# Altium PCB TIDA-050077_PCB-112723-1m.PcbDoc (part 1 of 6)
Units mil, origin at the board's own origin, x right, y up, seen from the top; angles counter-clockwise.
Board outline 3780 x 7750 mil, 16 copper layers (Top Layer, L2-Powet 1, L3-Power 2, L4-Power 3, L5-Power 4, L6-INT 1, L7-INT 2, L8-INT 3, L9-INT 4, L10-INT 5, L11-INT 6, L12-Power 5, L13-Power 6, L14-Power 7, L15-Power 8, Bottom Layer), stack 121.442 mil thick; 381 components, 136 nets, 958 pads, 3470 vias.
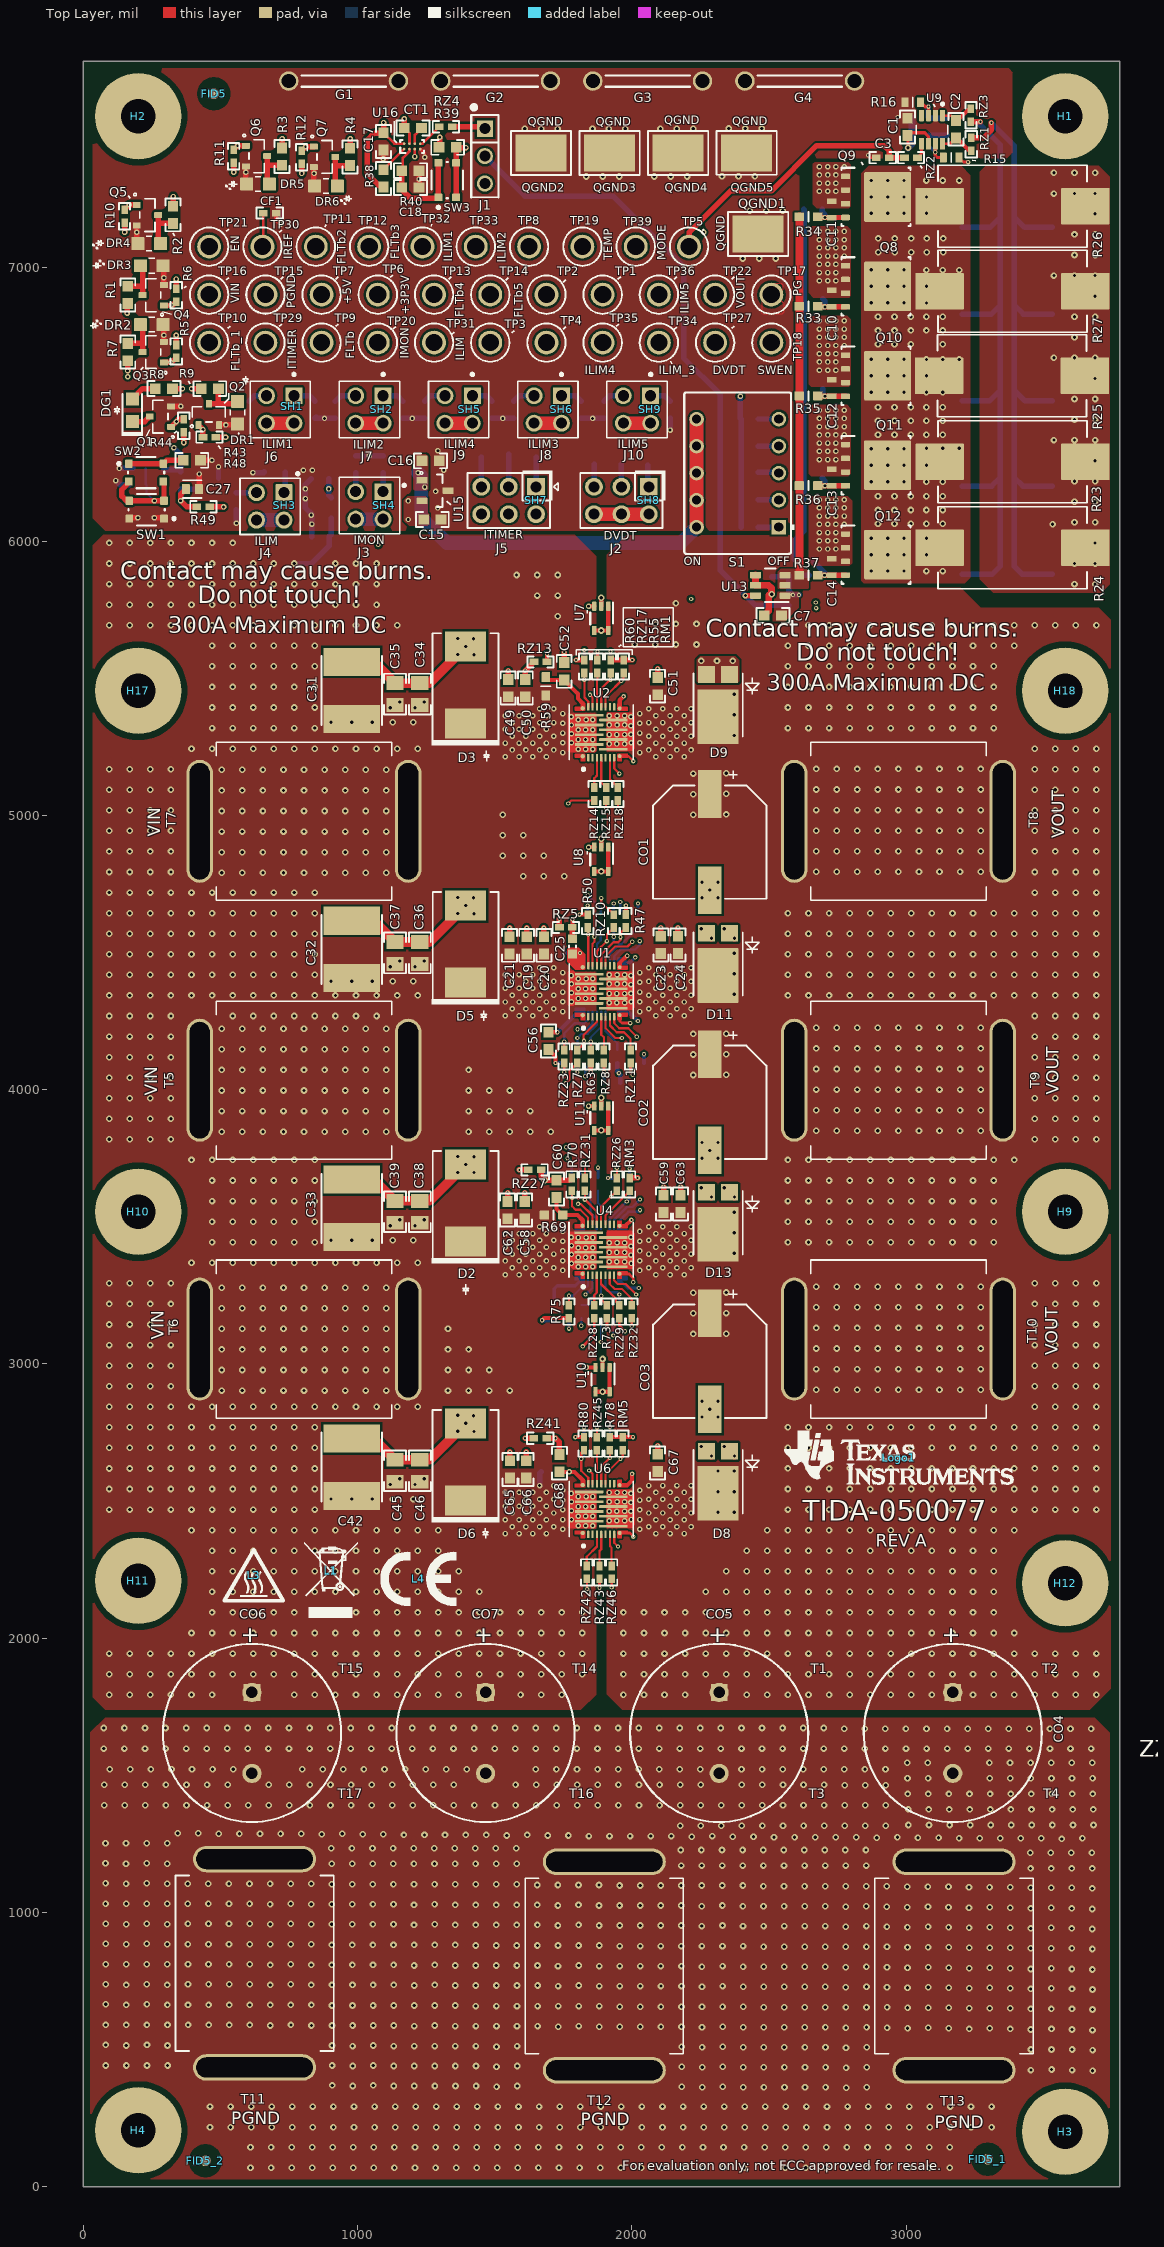
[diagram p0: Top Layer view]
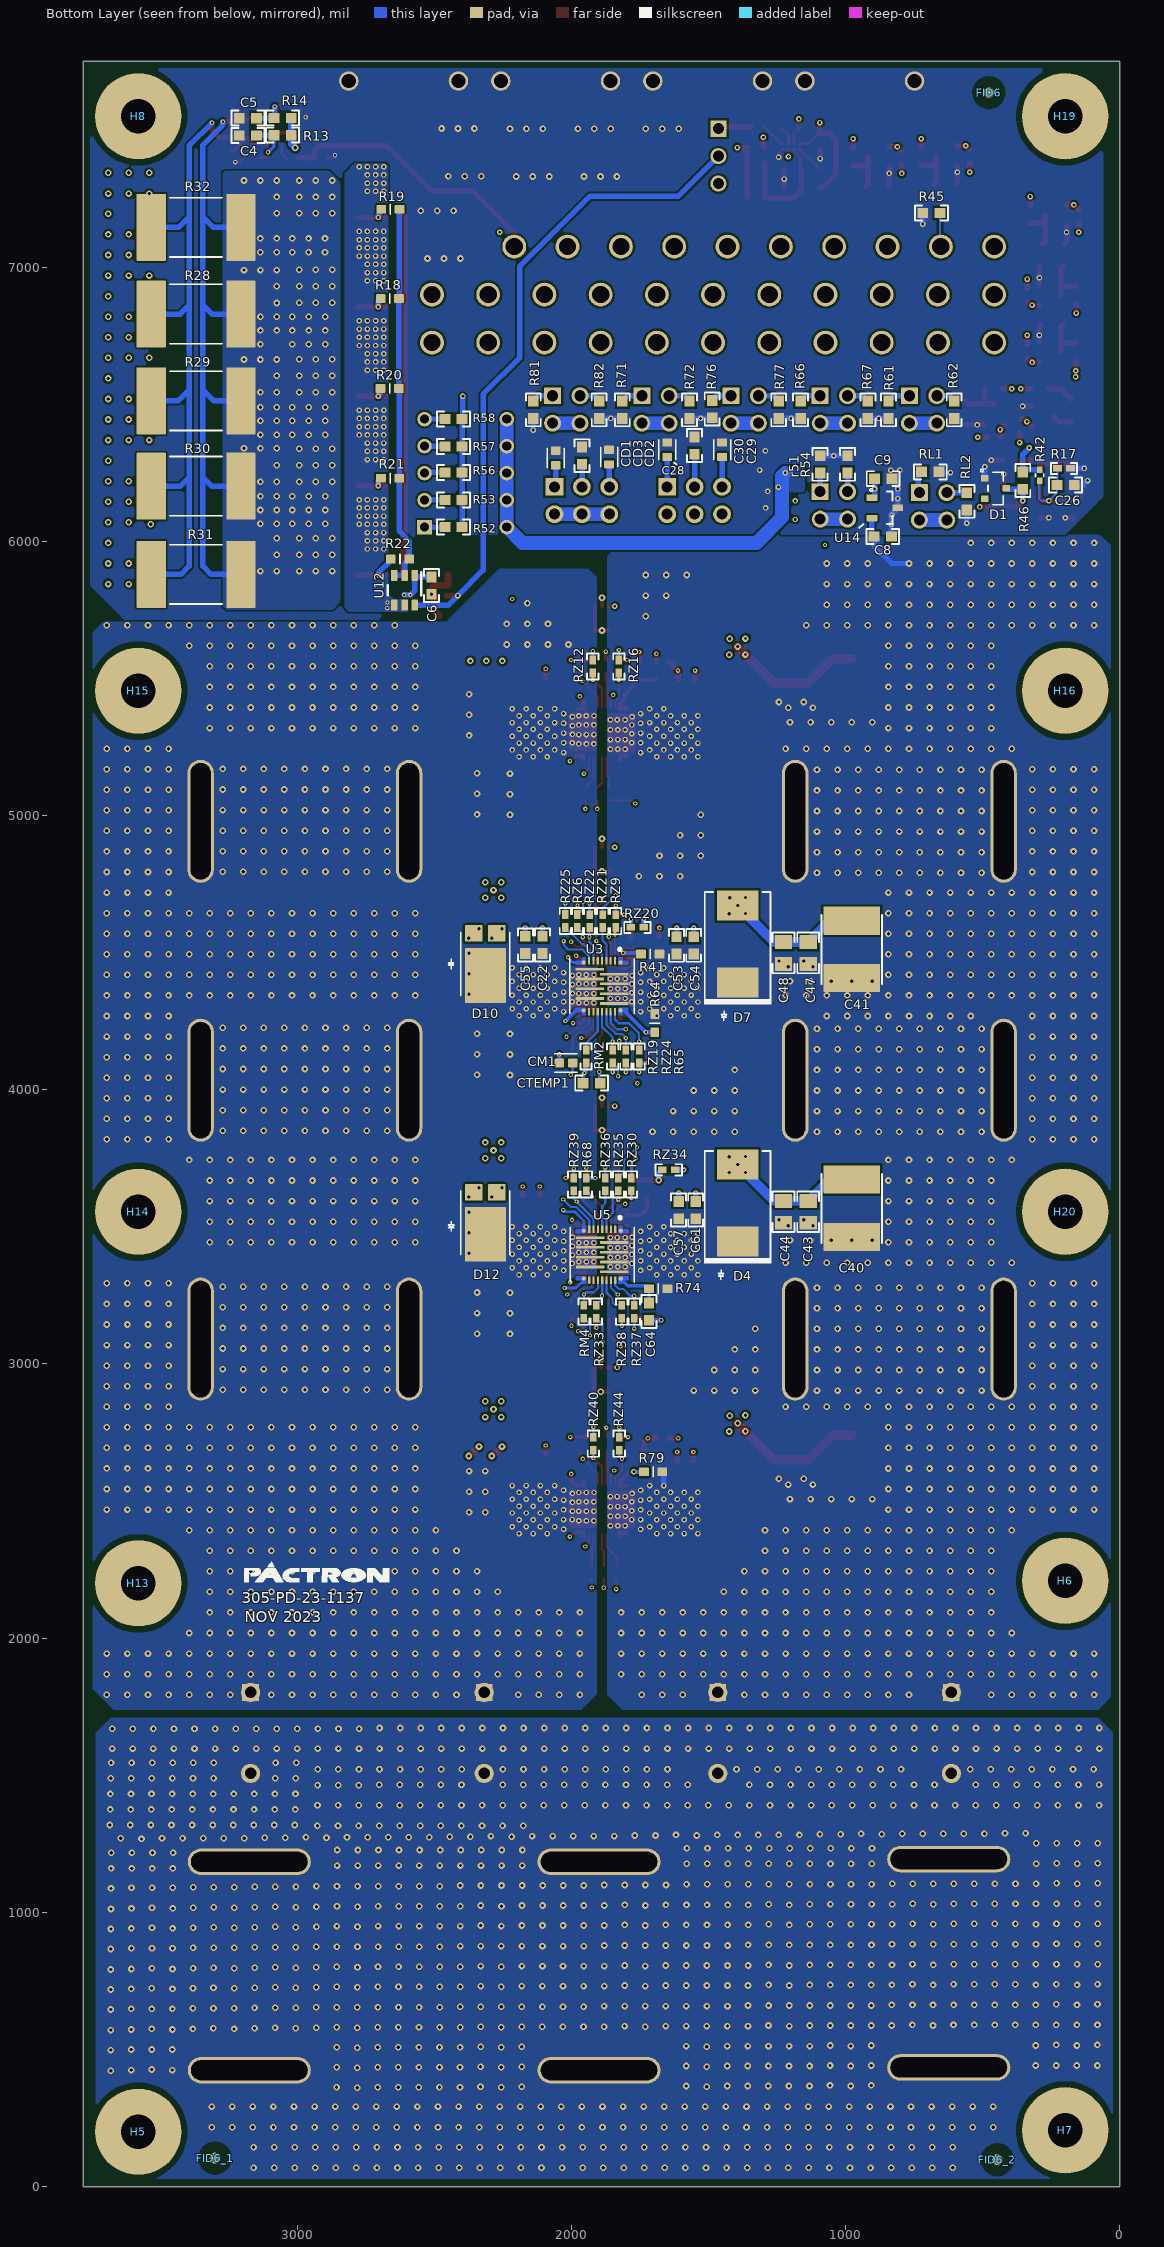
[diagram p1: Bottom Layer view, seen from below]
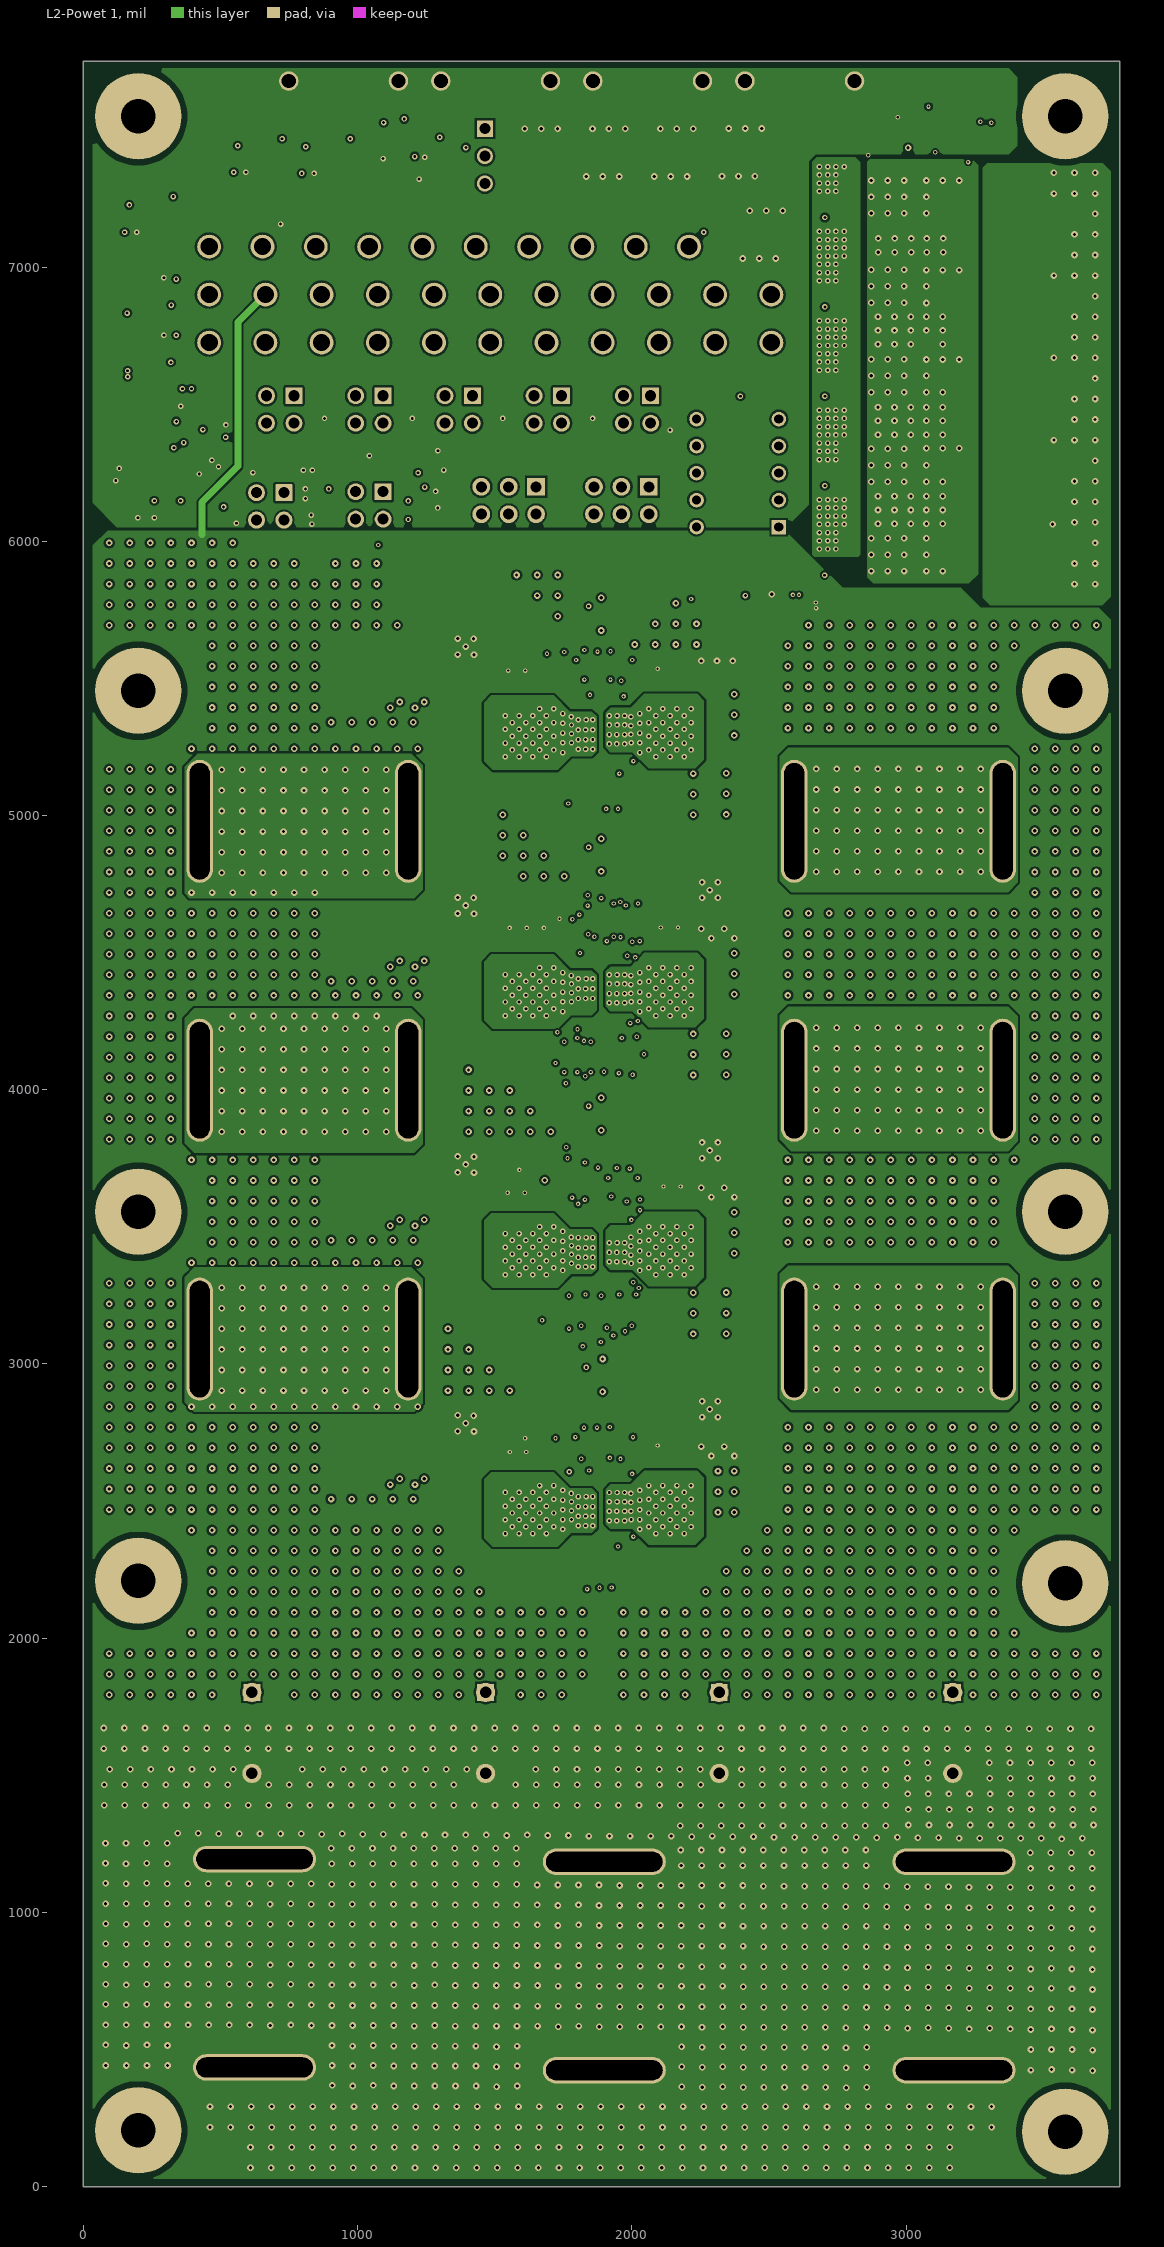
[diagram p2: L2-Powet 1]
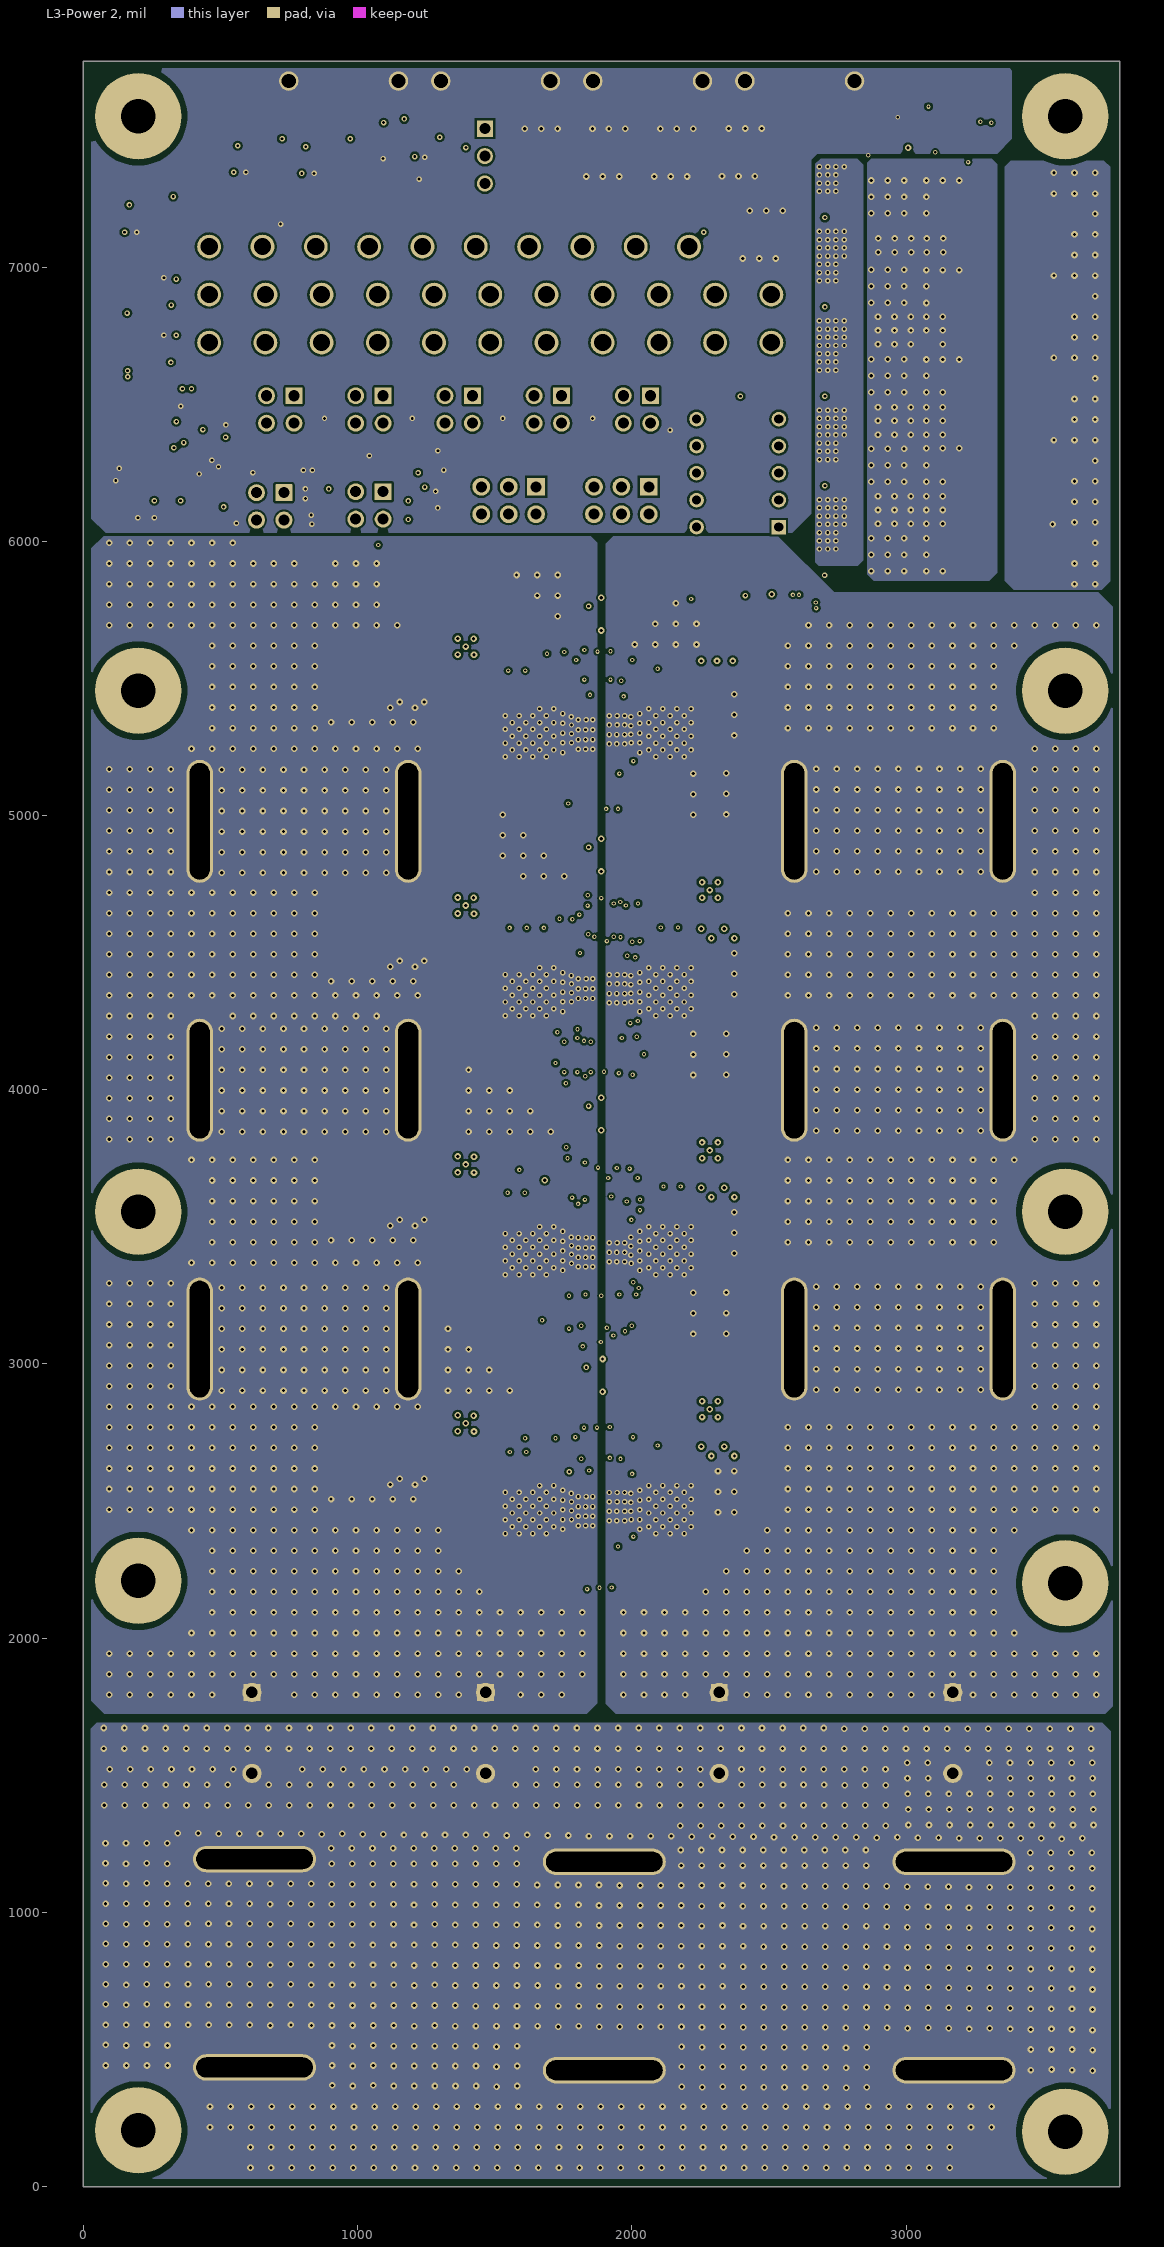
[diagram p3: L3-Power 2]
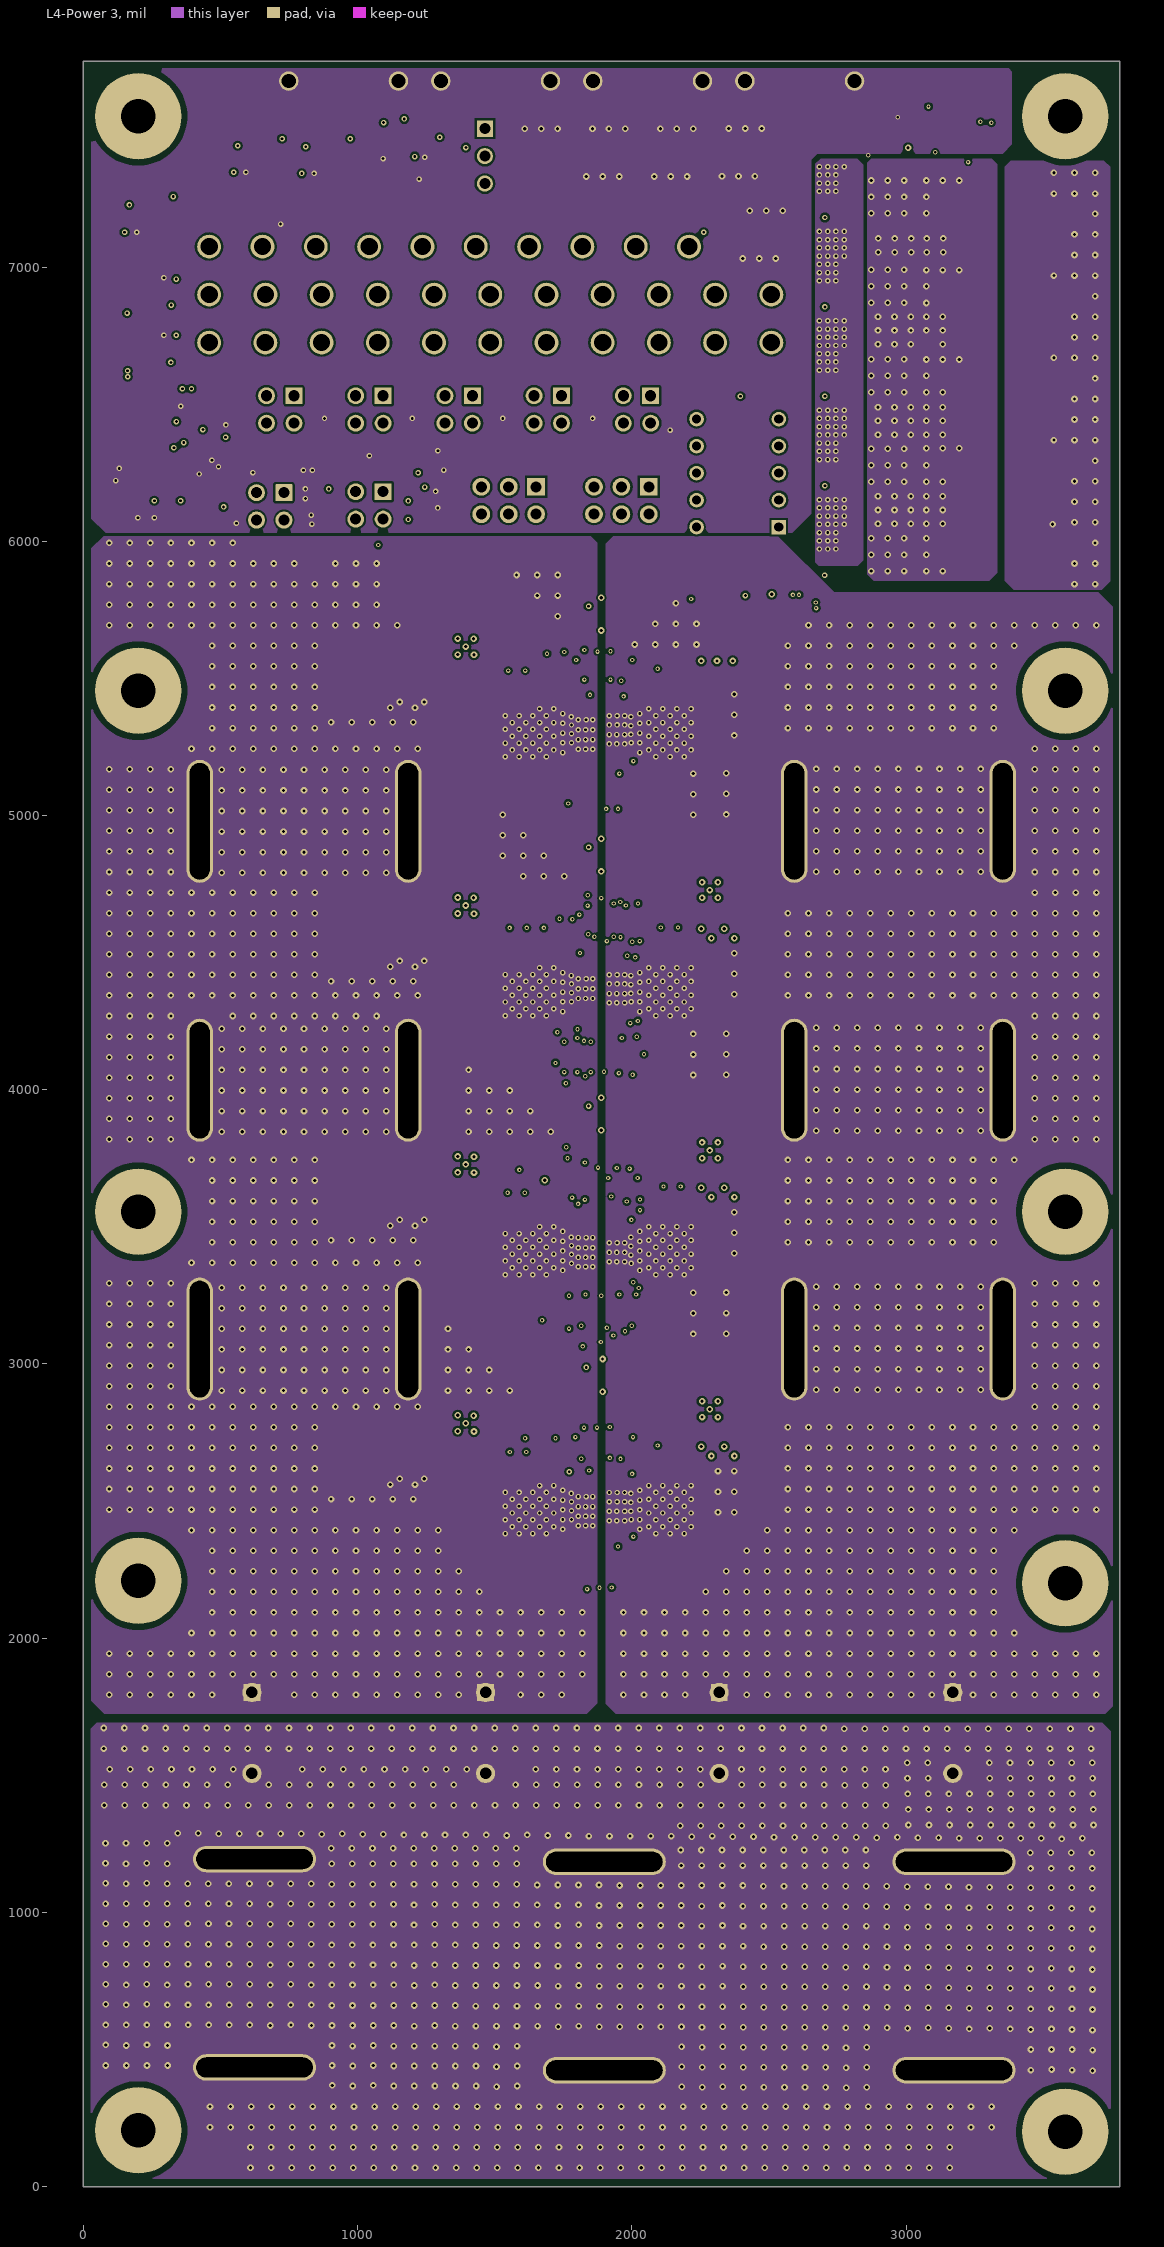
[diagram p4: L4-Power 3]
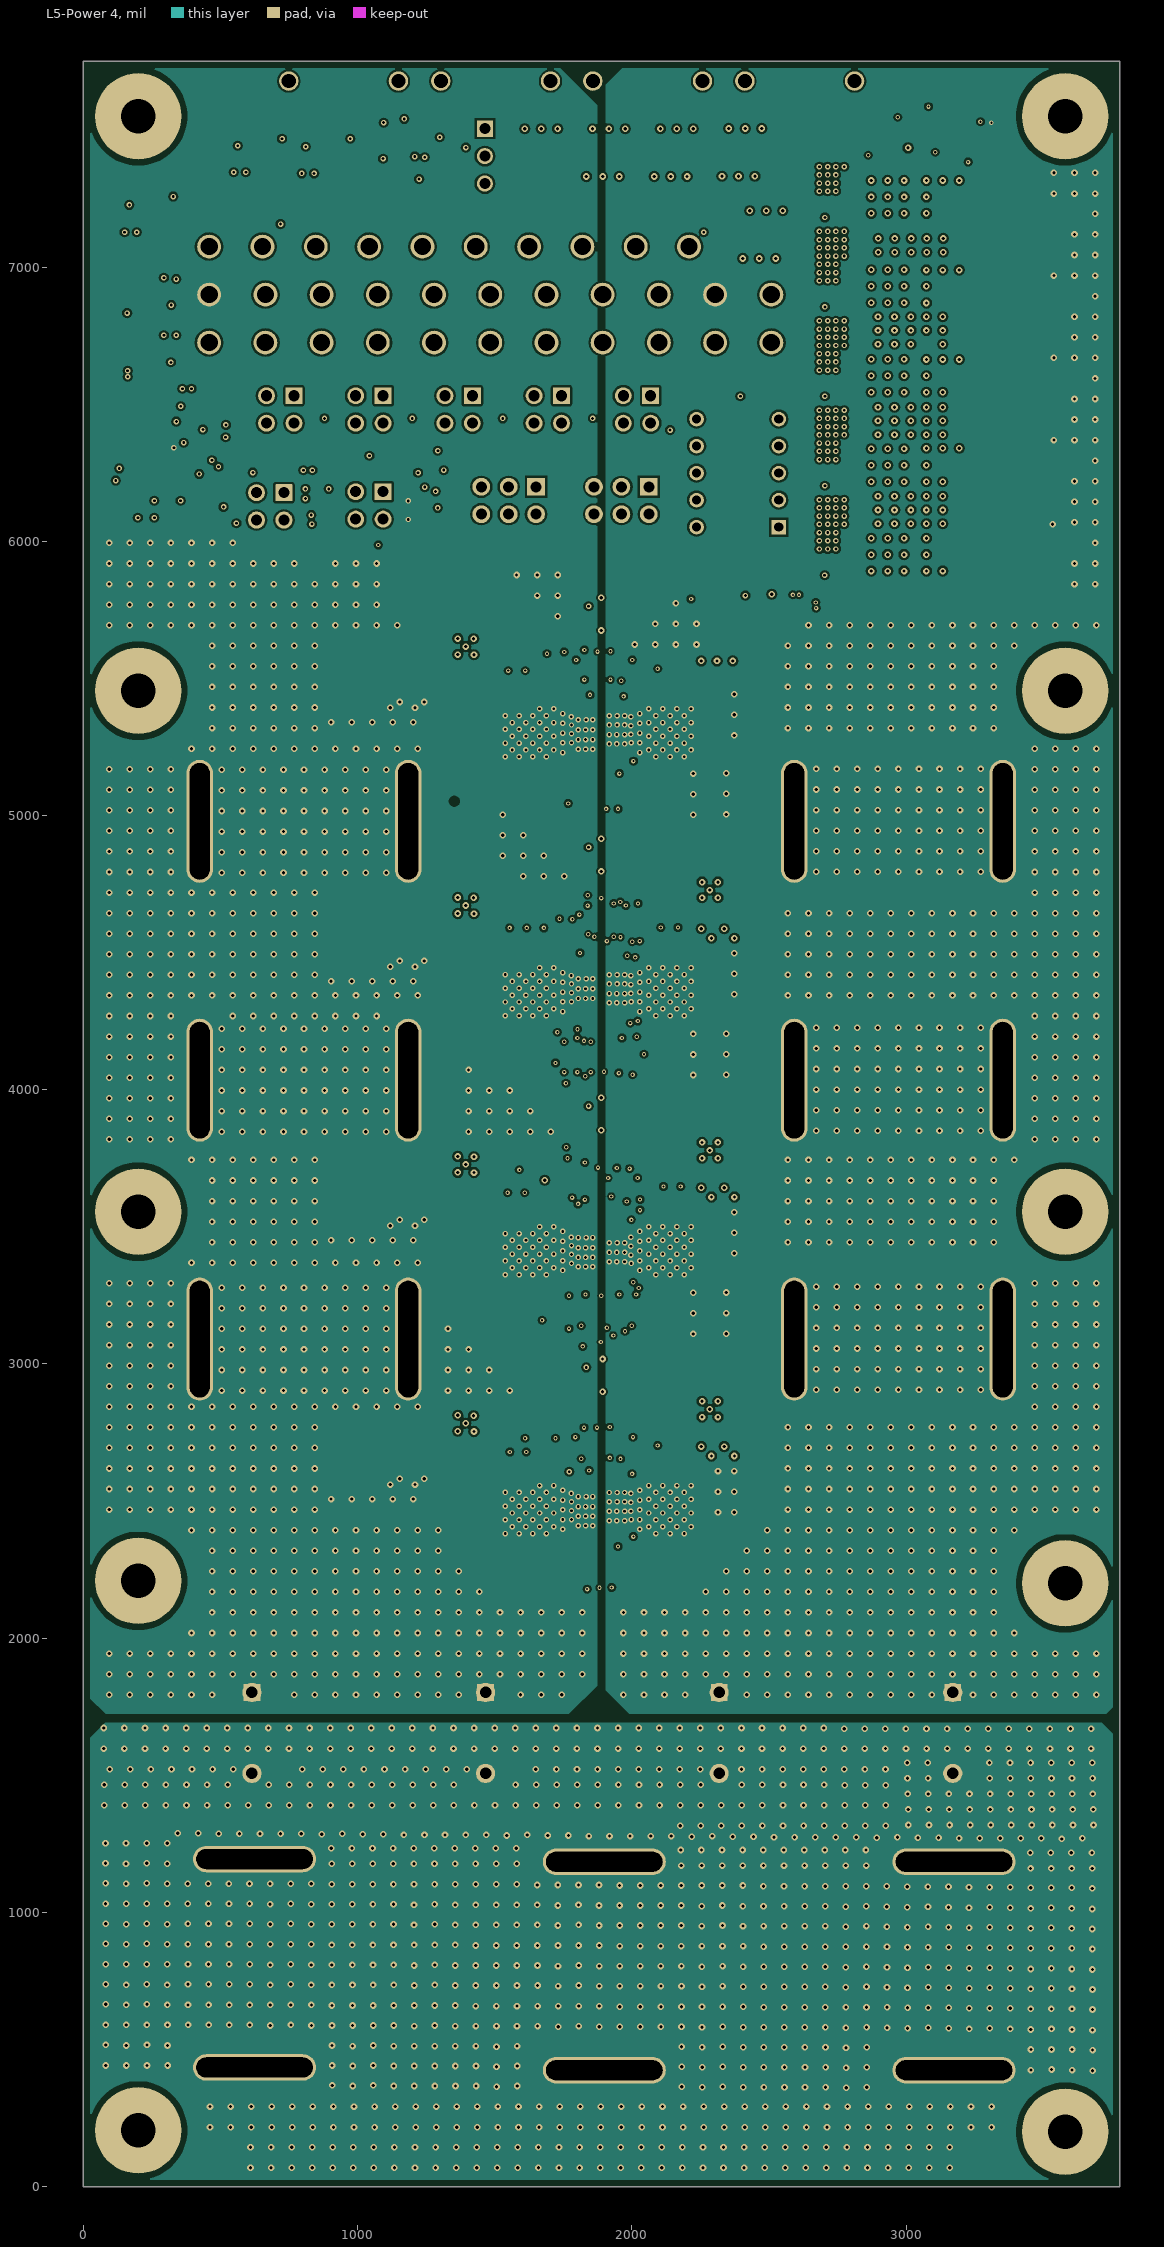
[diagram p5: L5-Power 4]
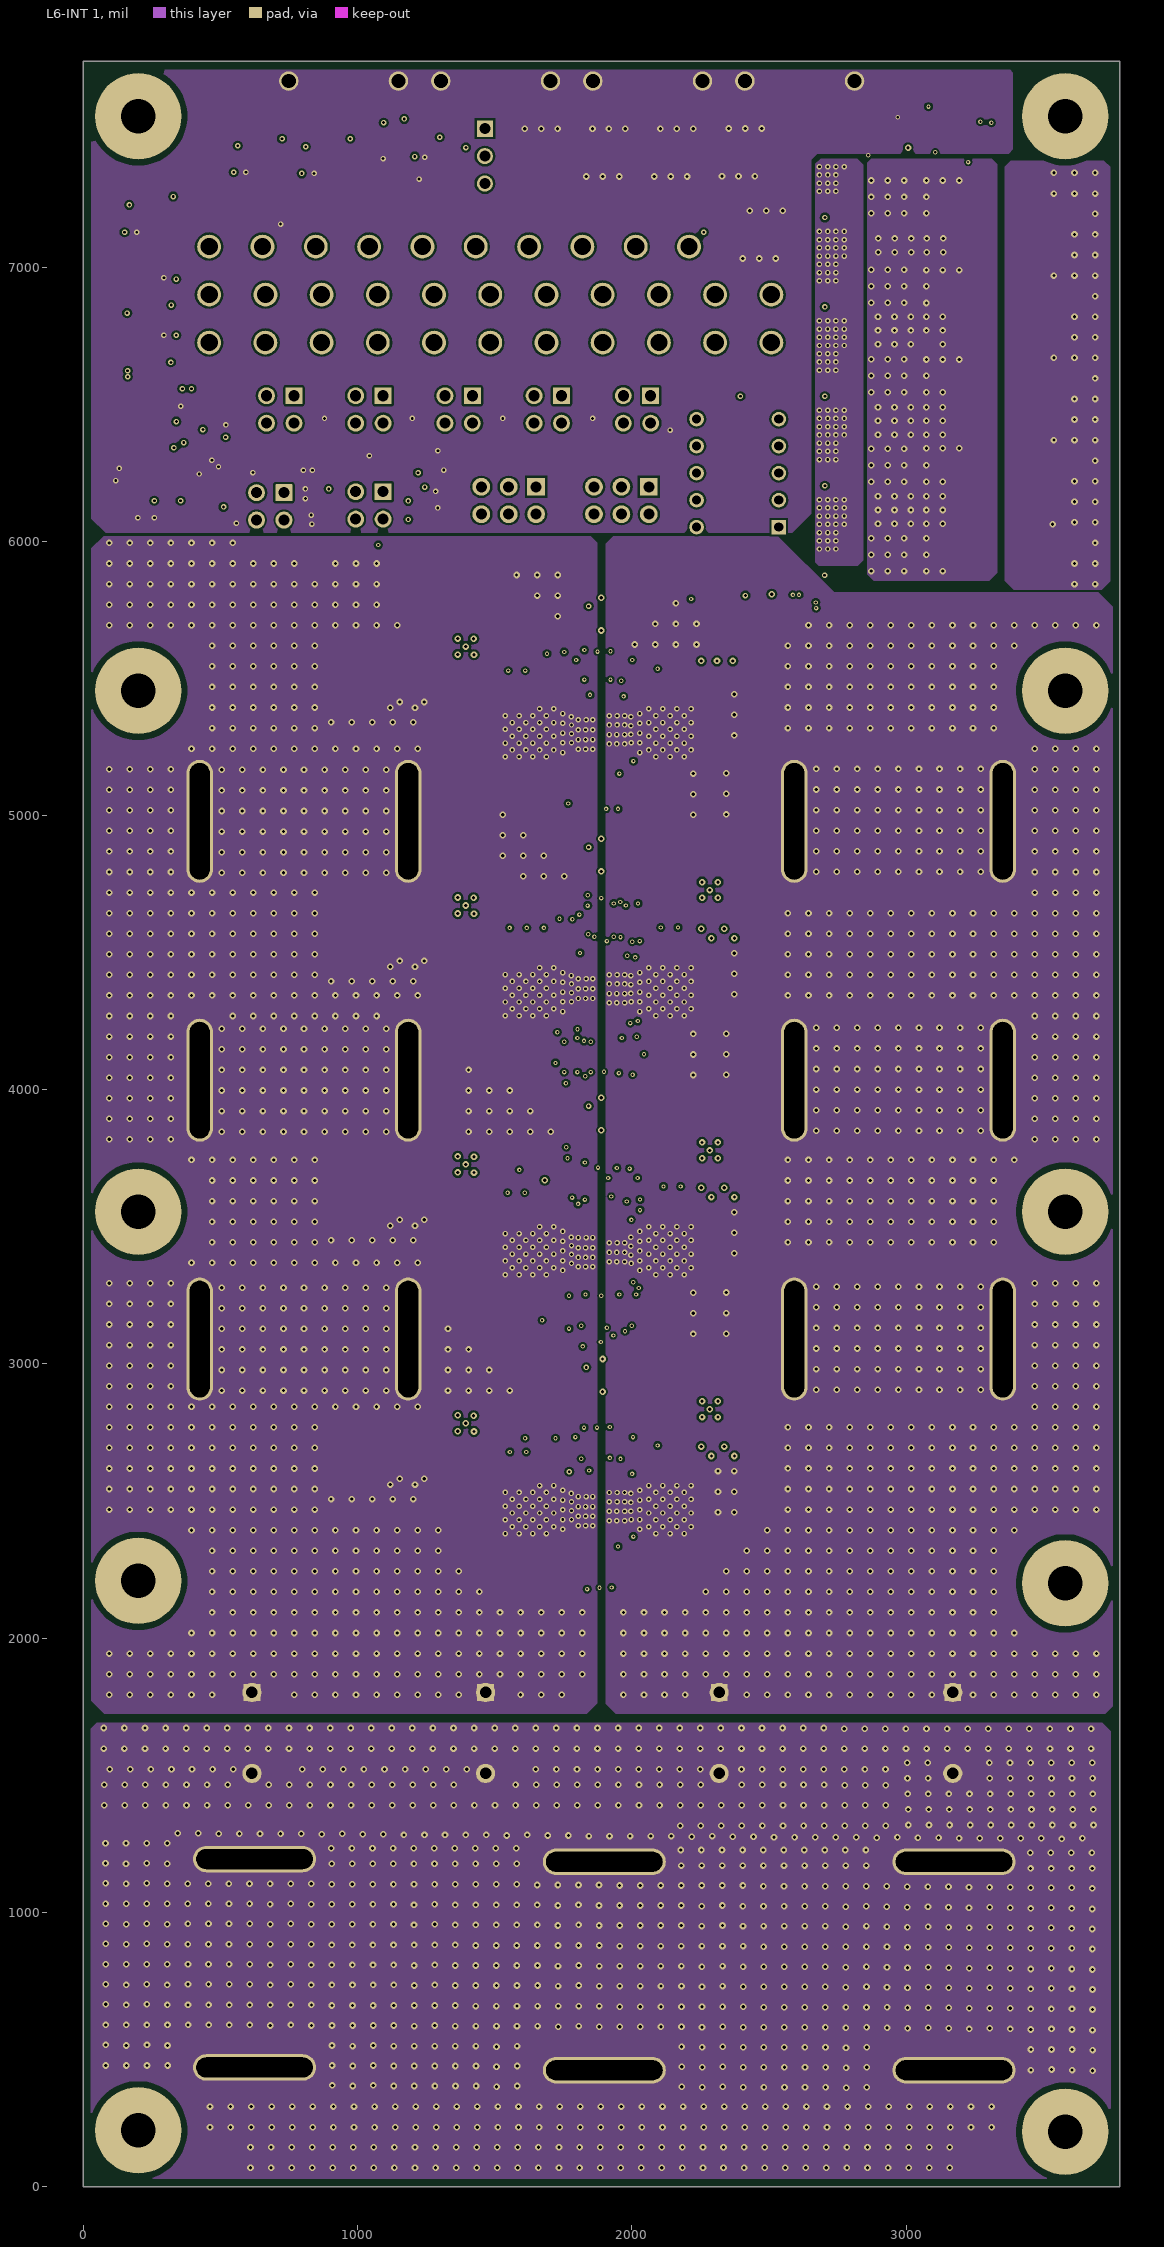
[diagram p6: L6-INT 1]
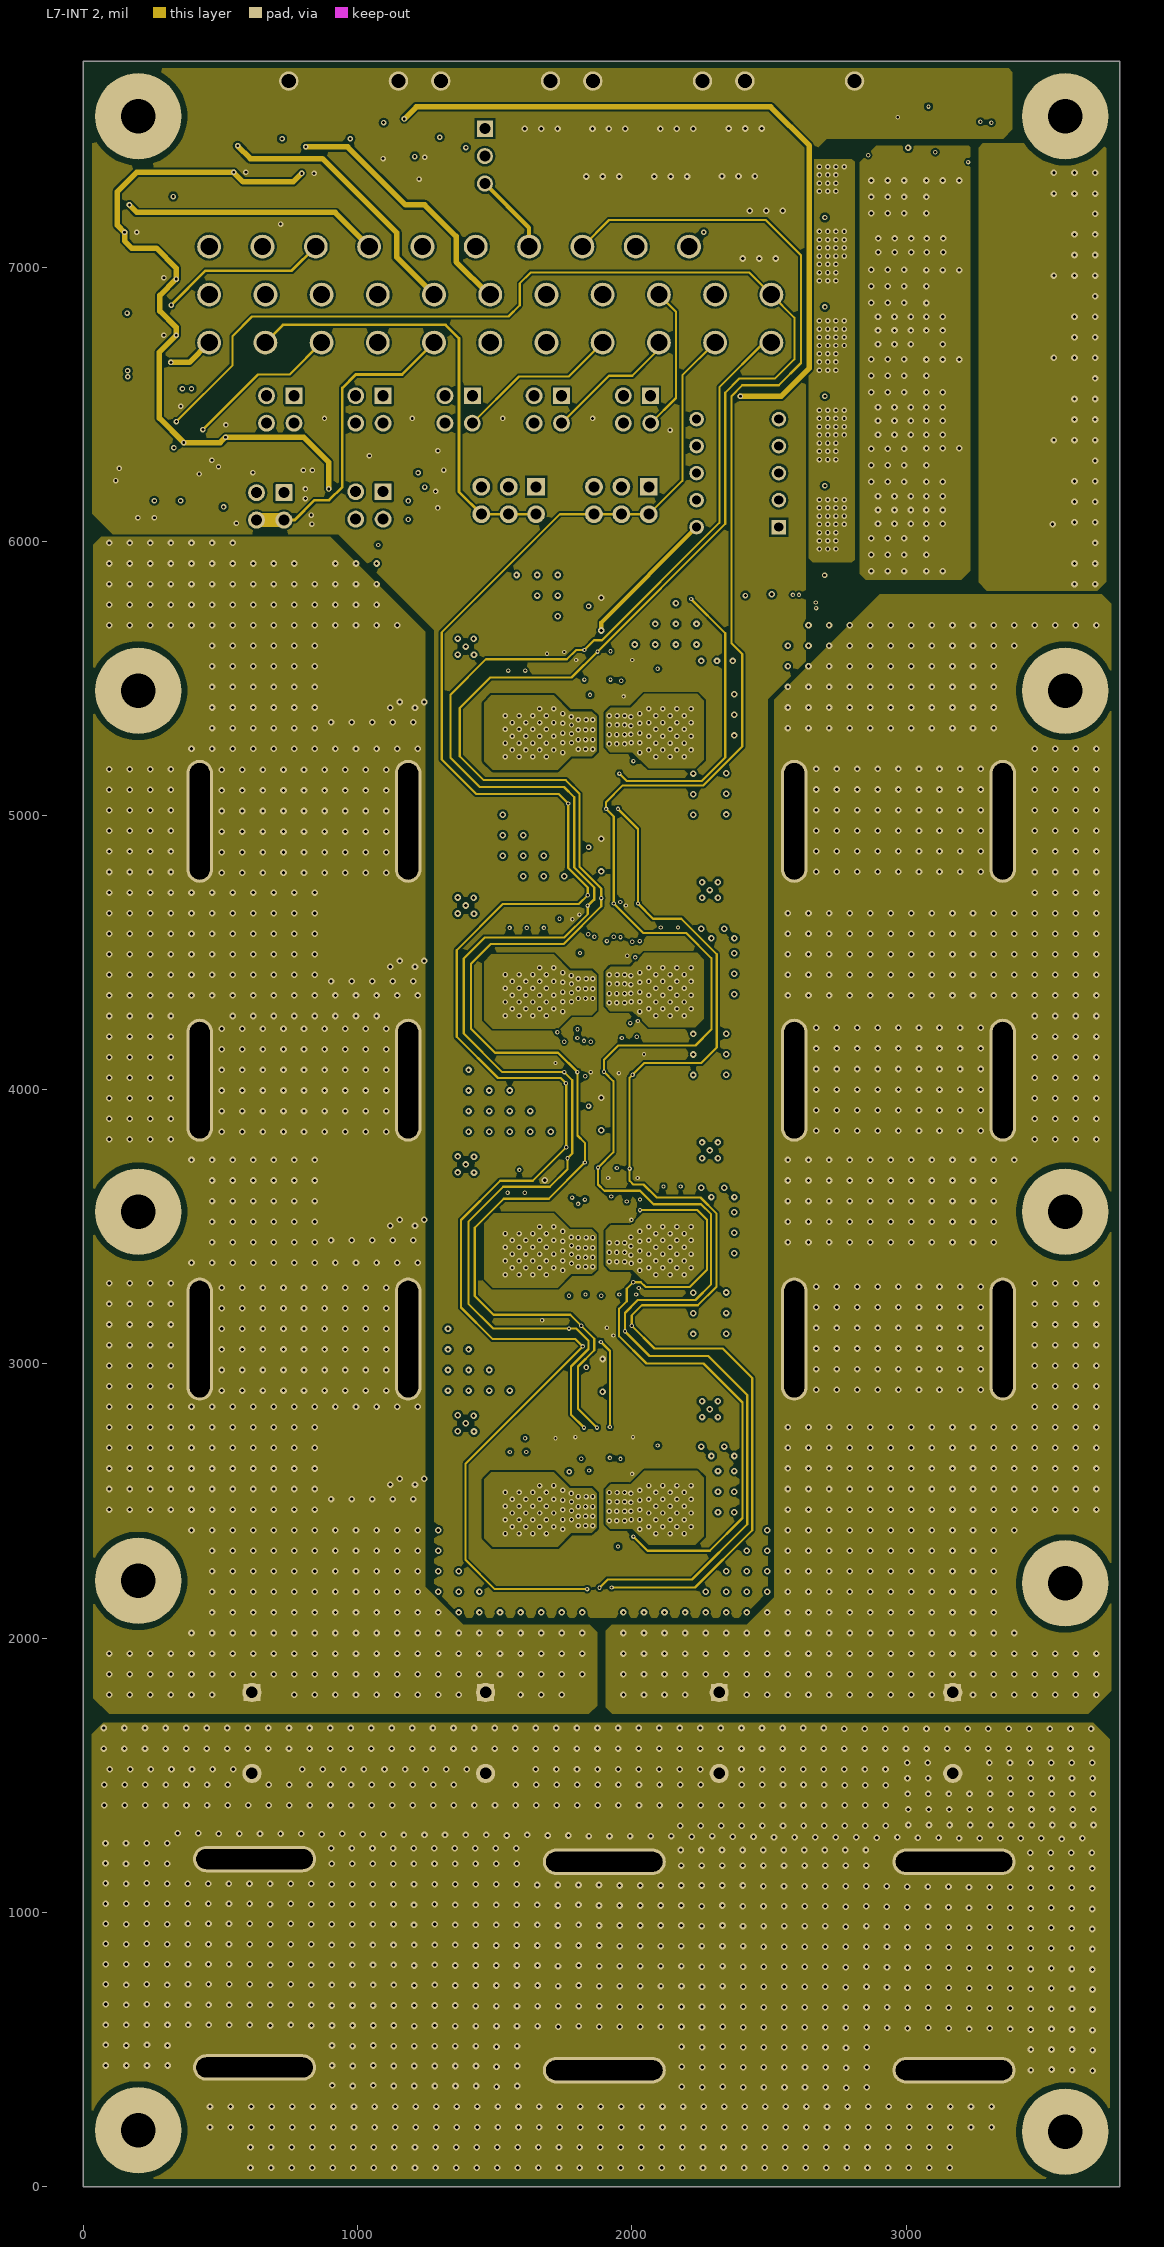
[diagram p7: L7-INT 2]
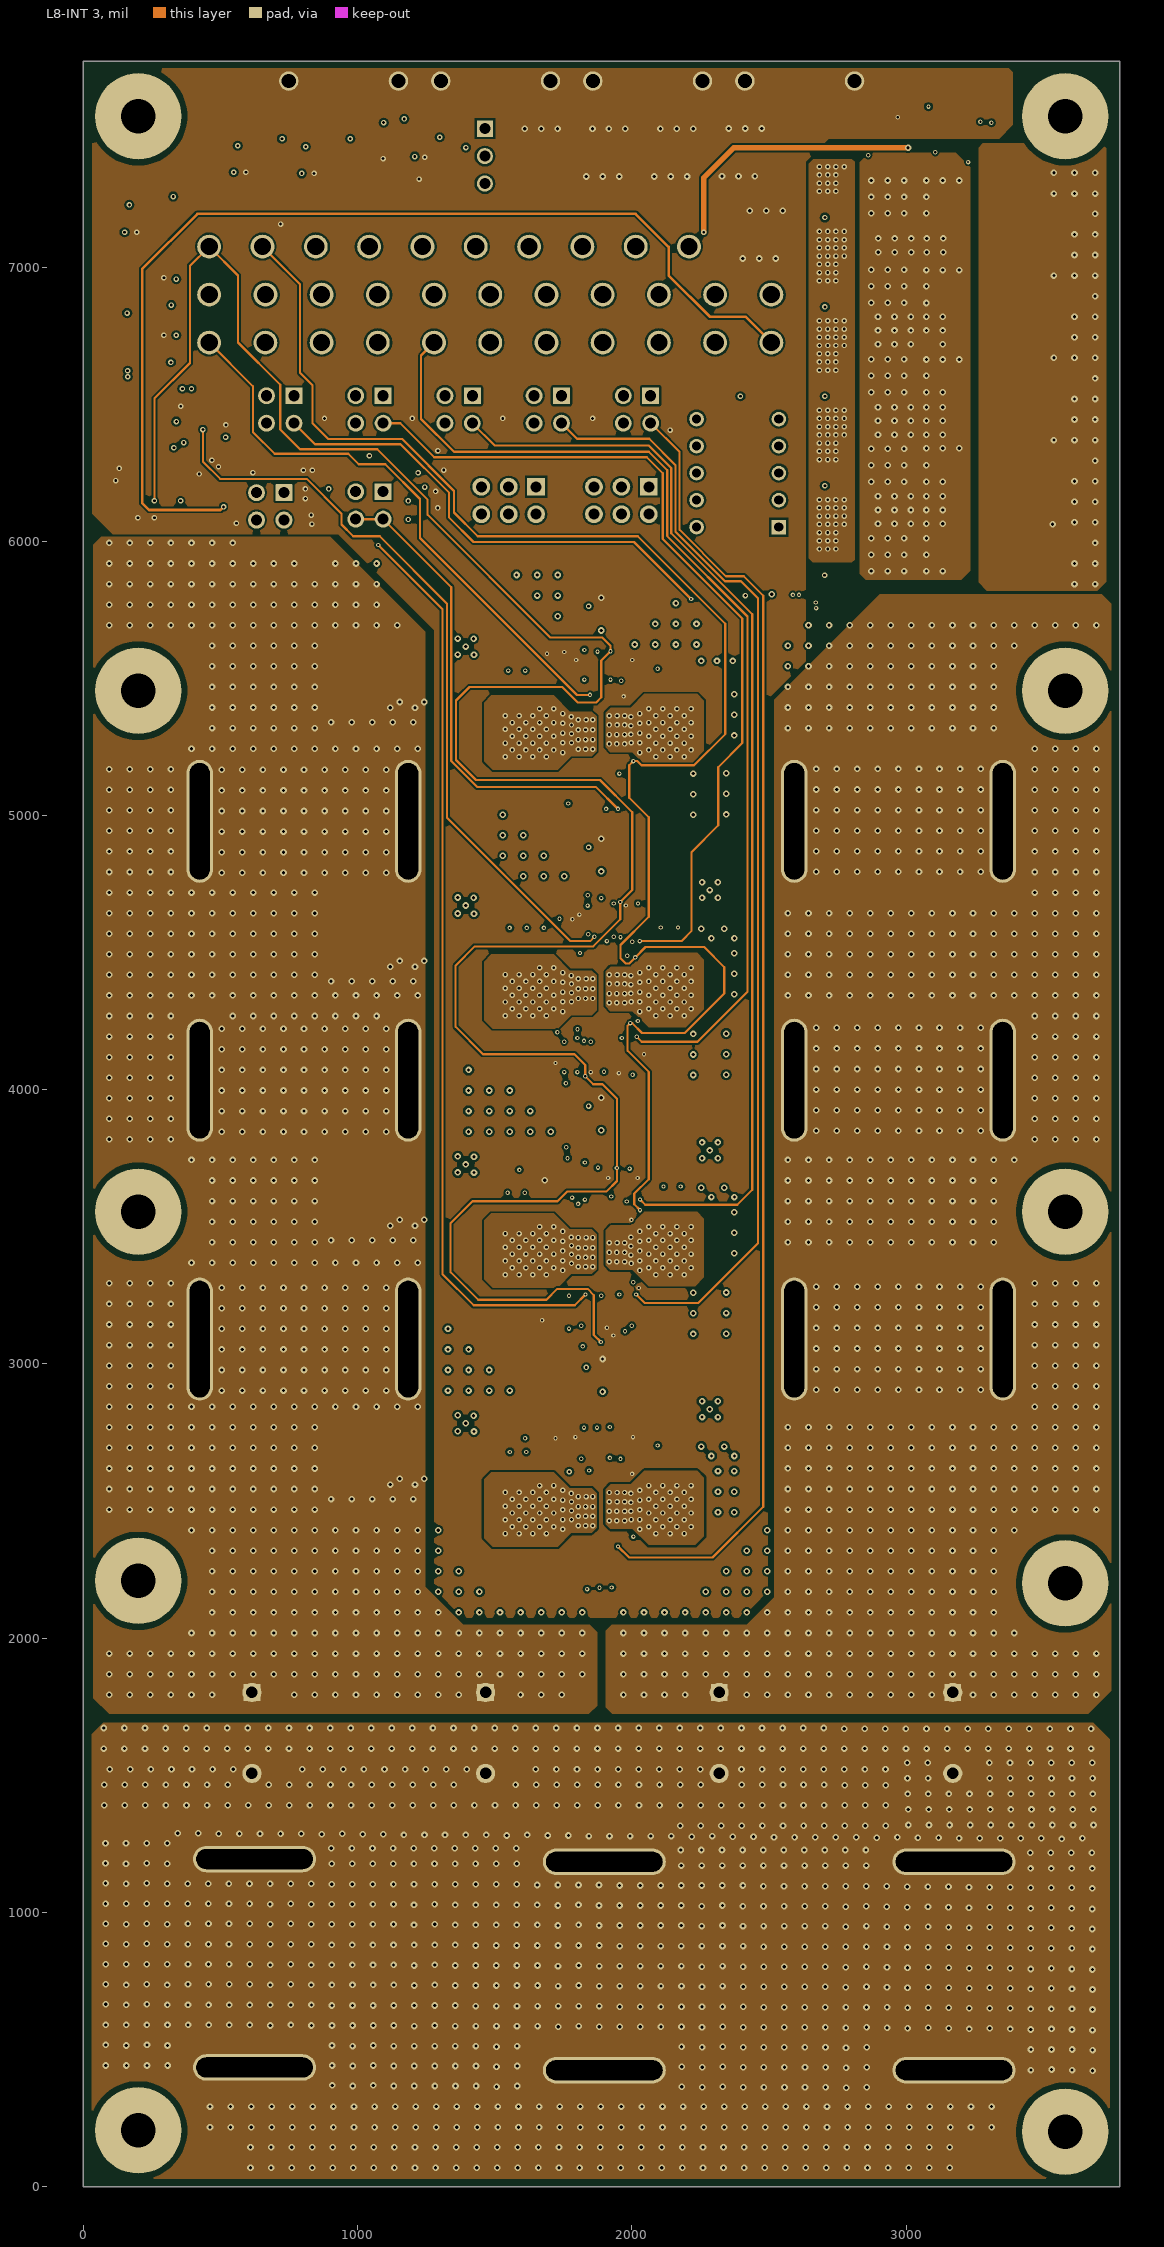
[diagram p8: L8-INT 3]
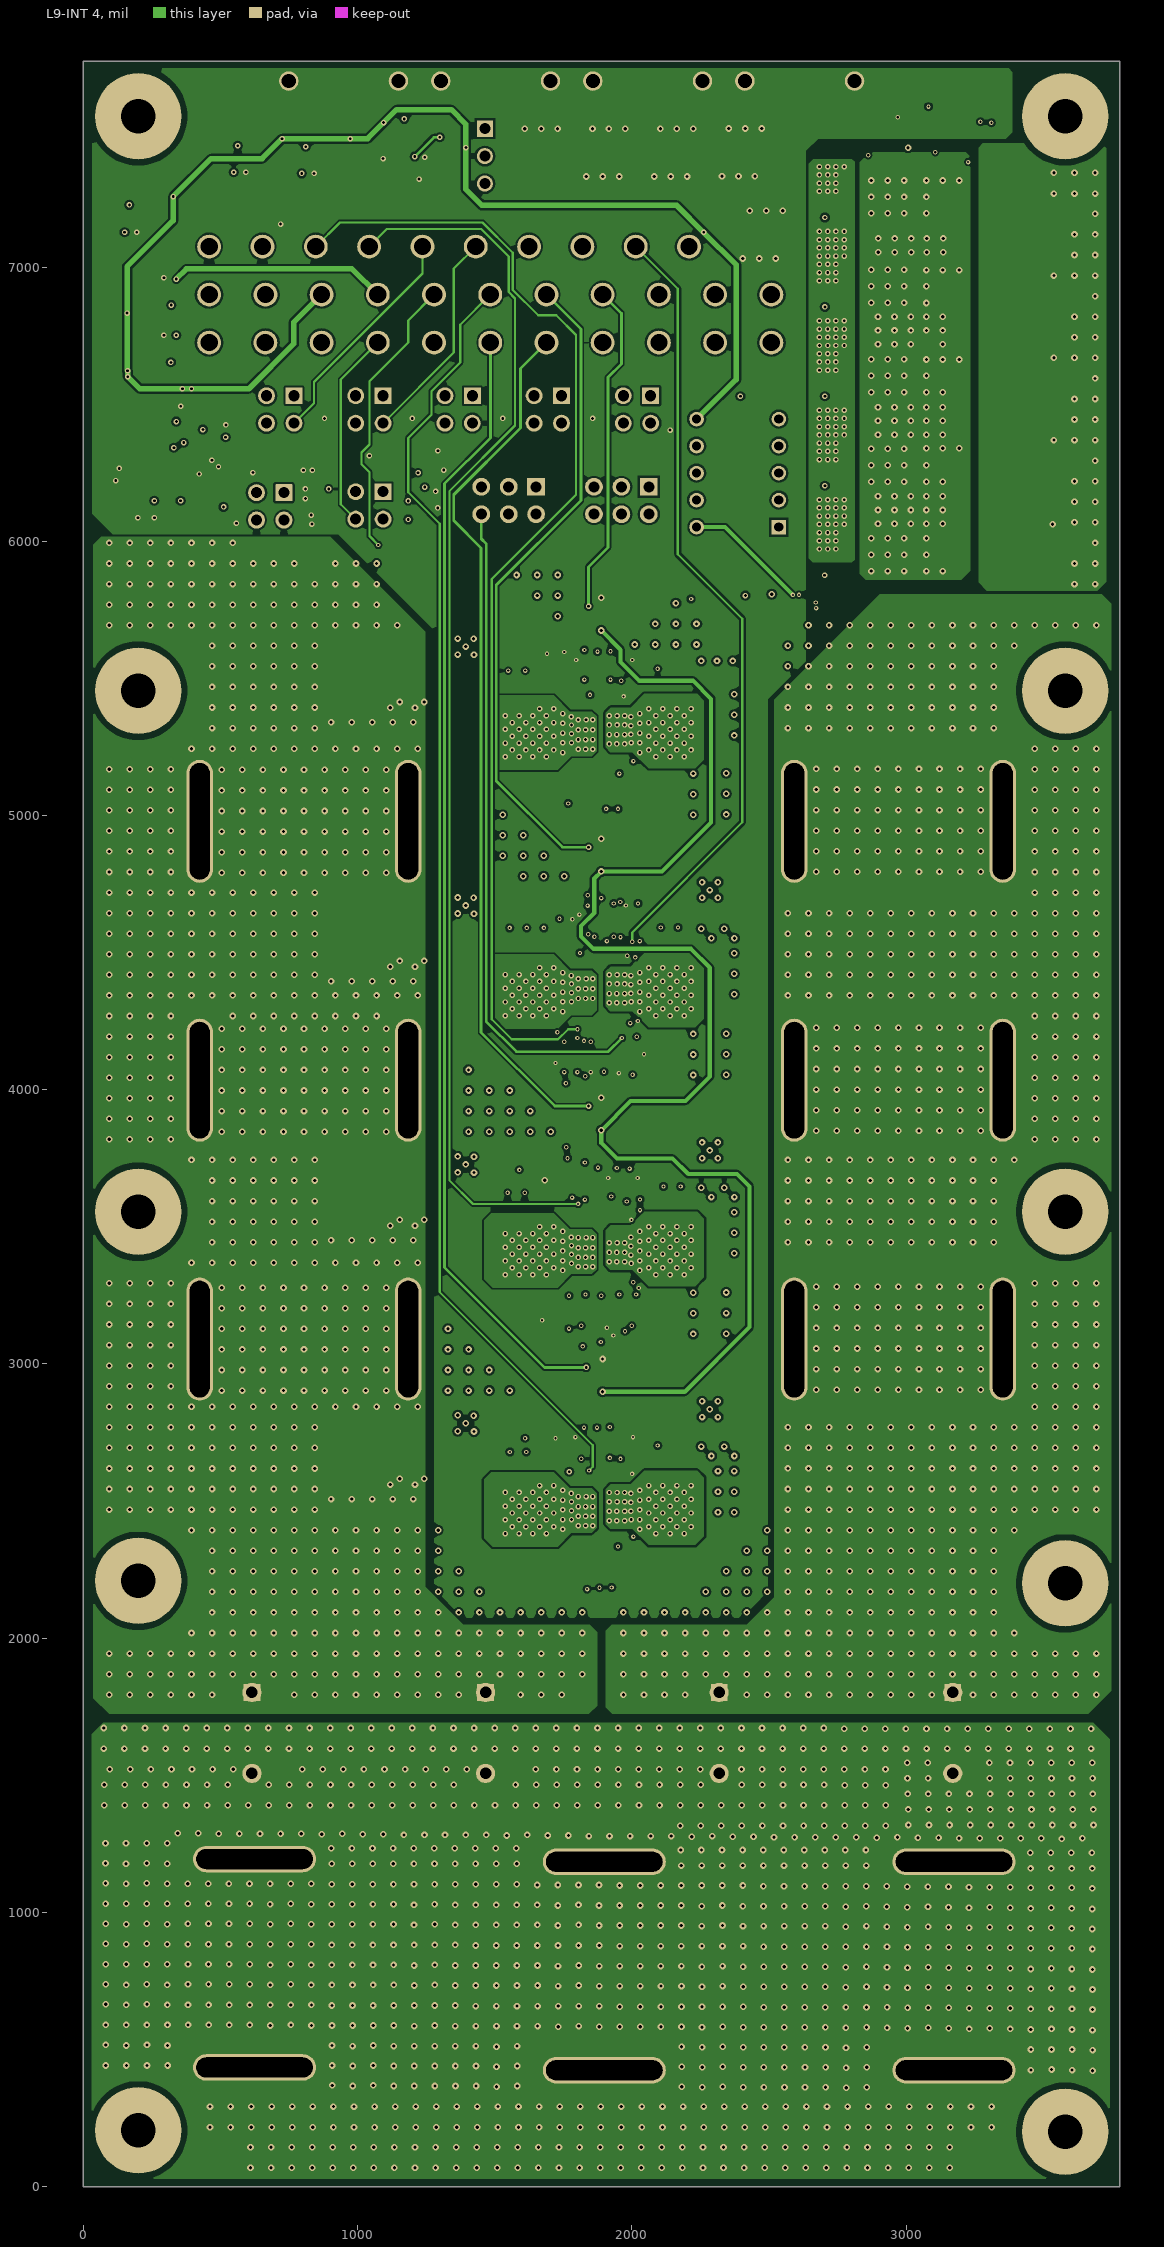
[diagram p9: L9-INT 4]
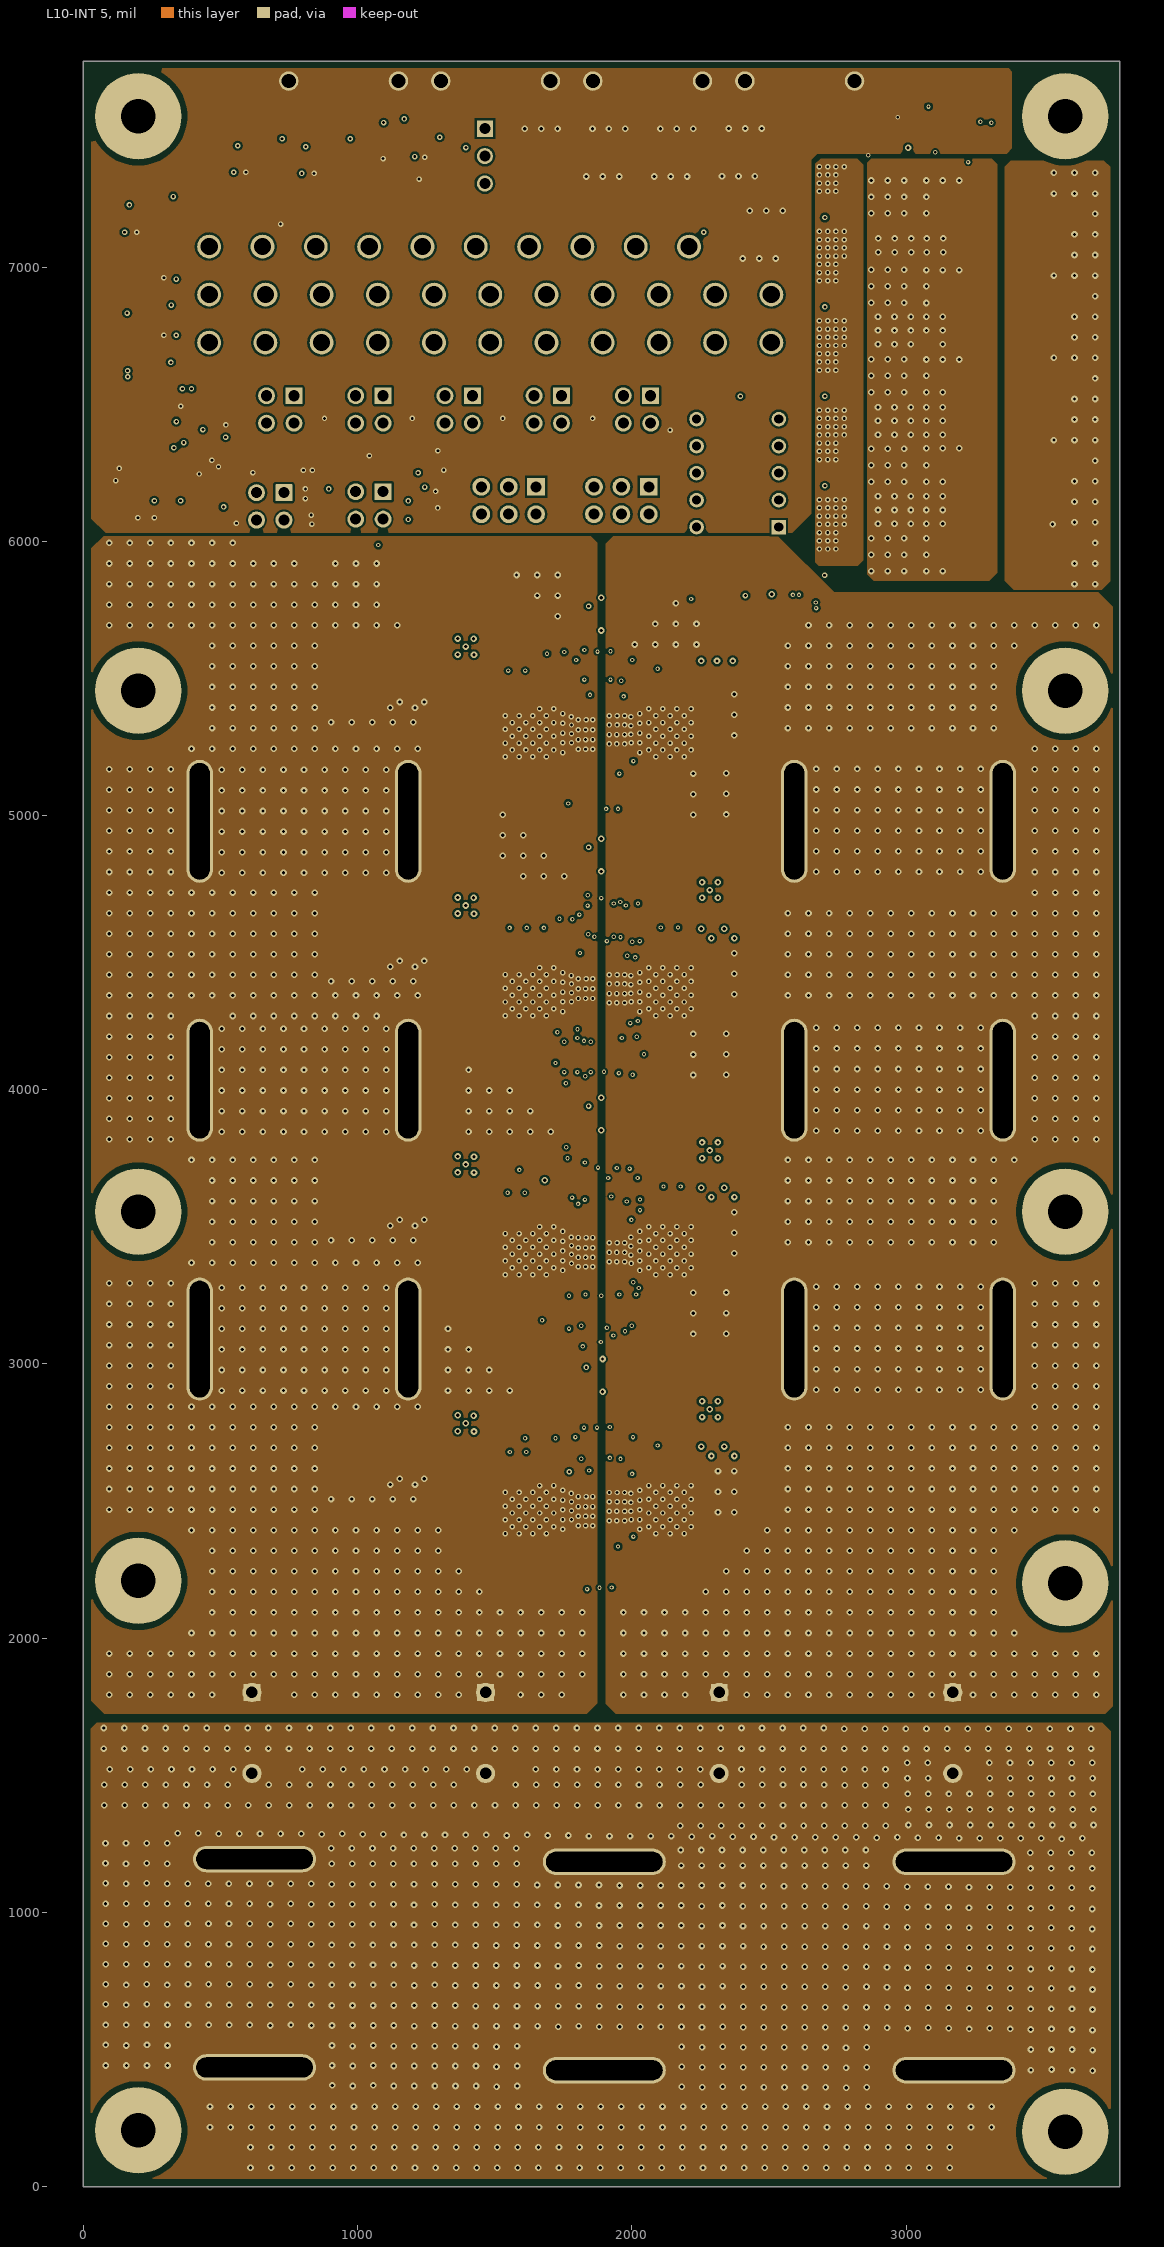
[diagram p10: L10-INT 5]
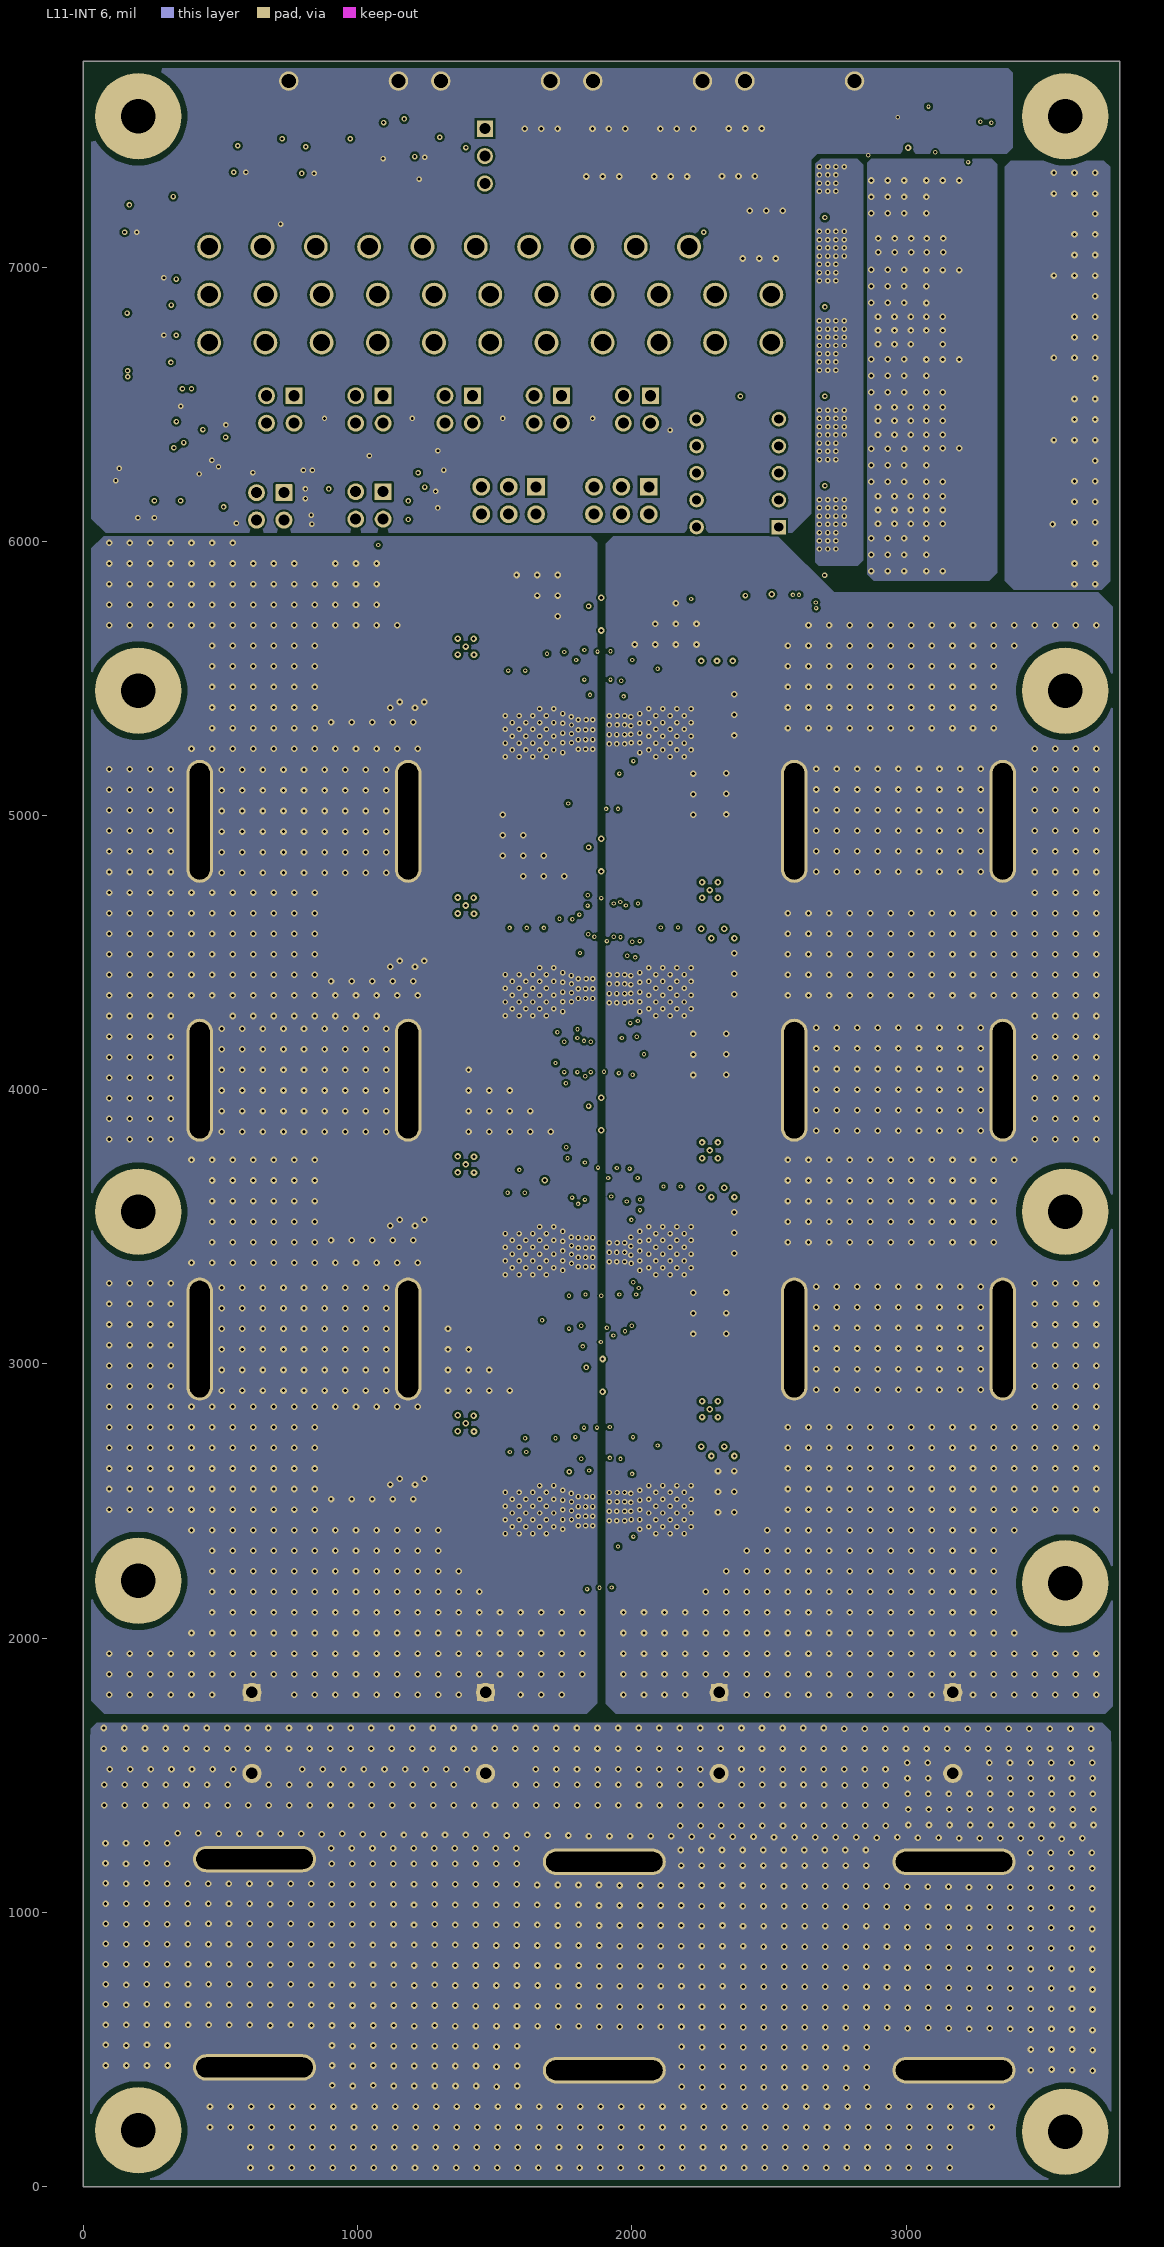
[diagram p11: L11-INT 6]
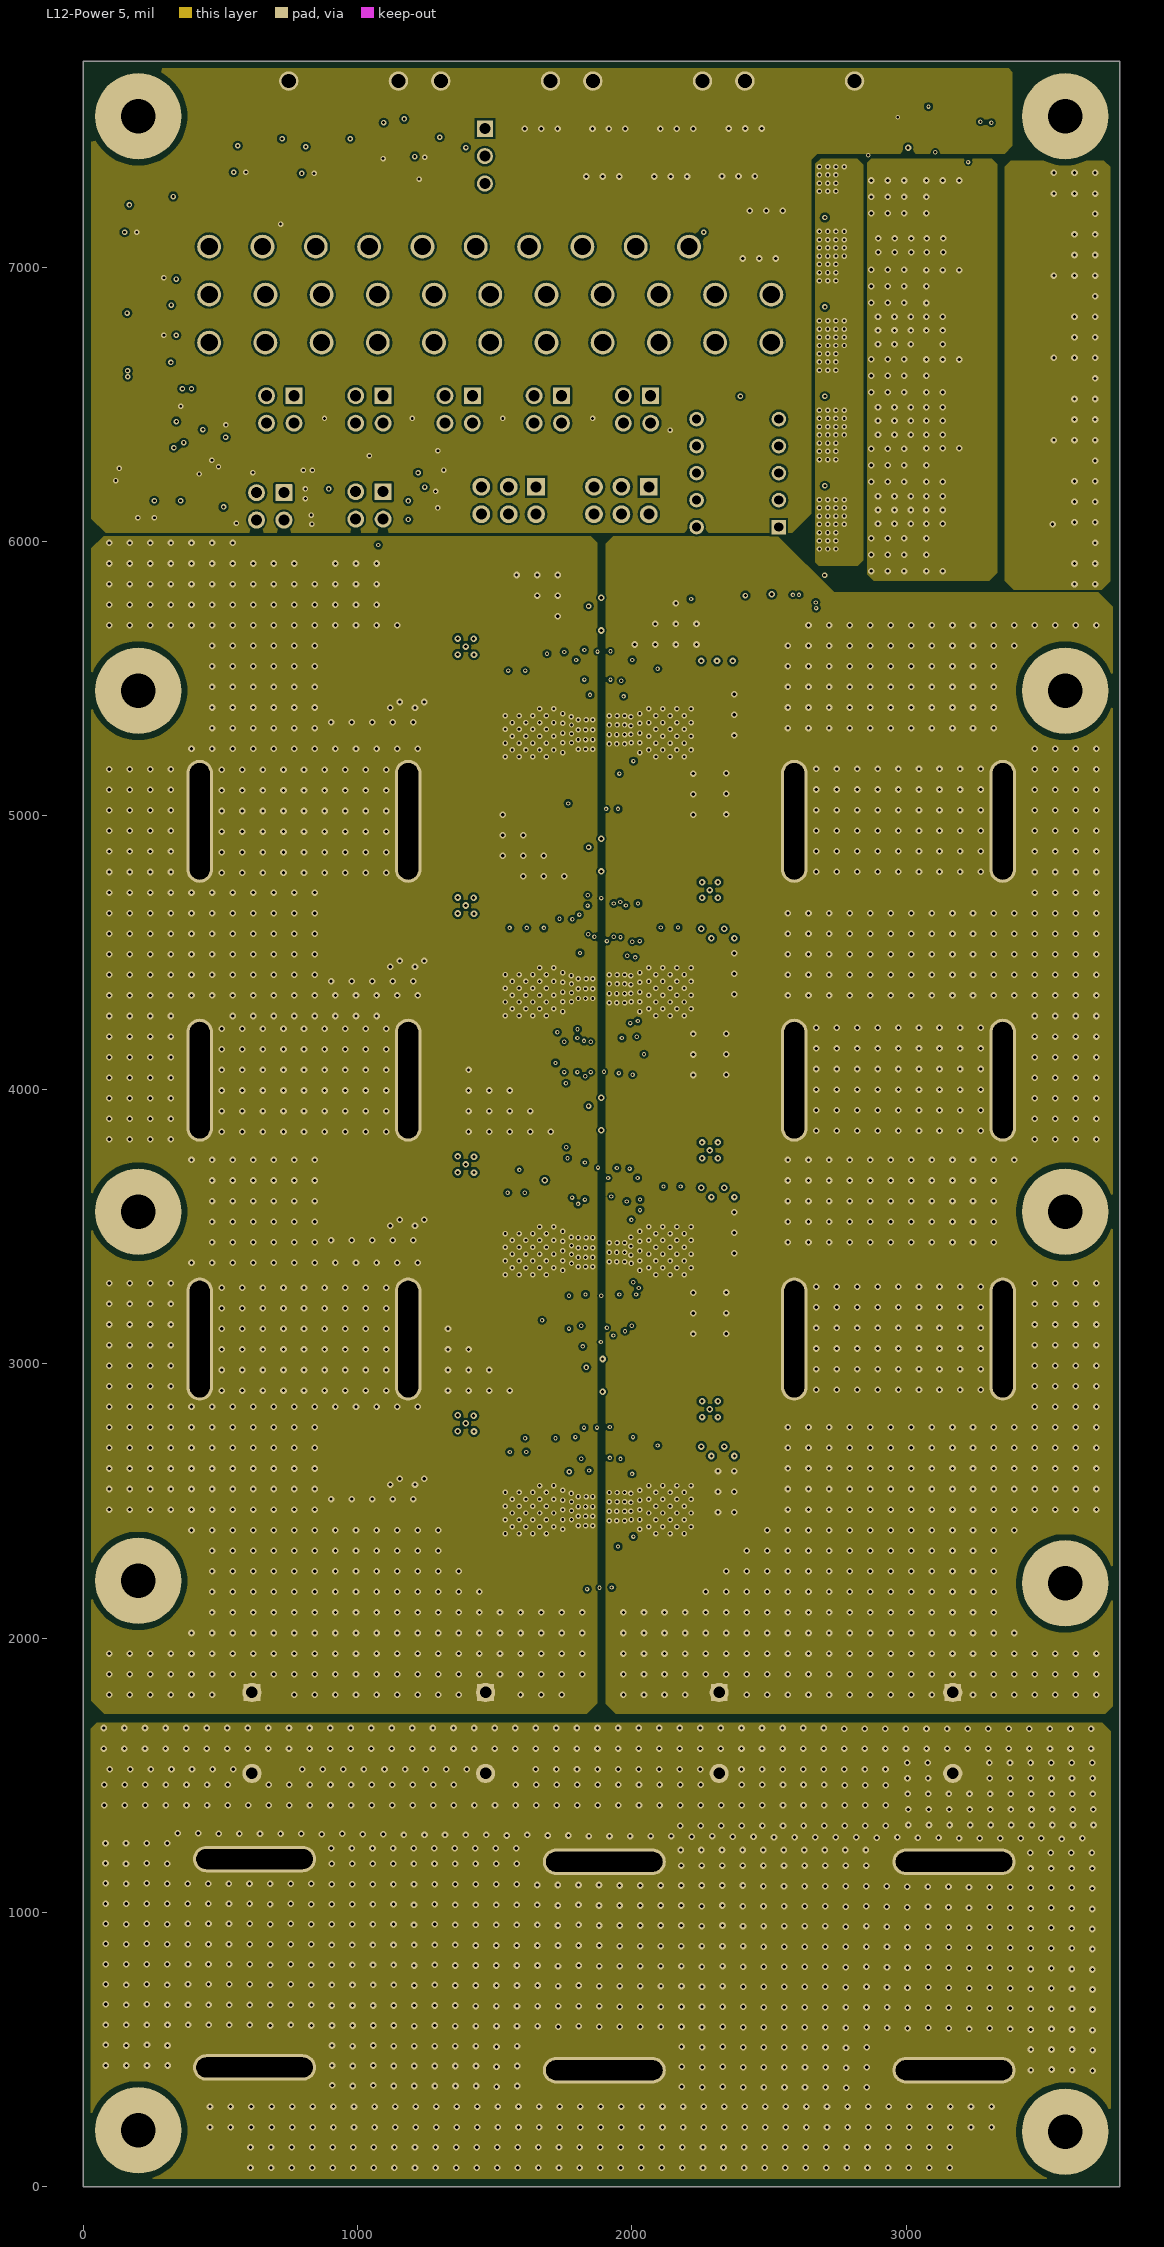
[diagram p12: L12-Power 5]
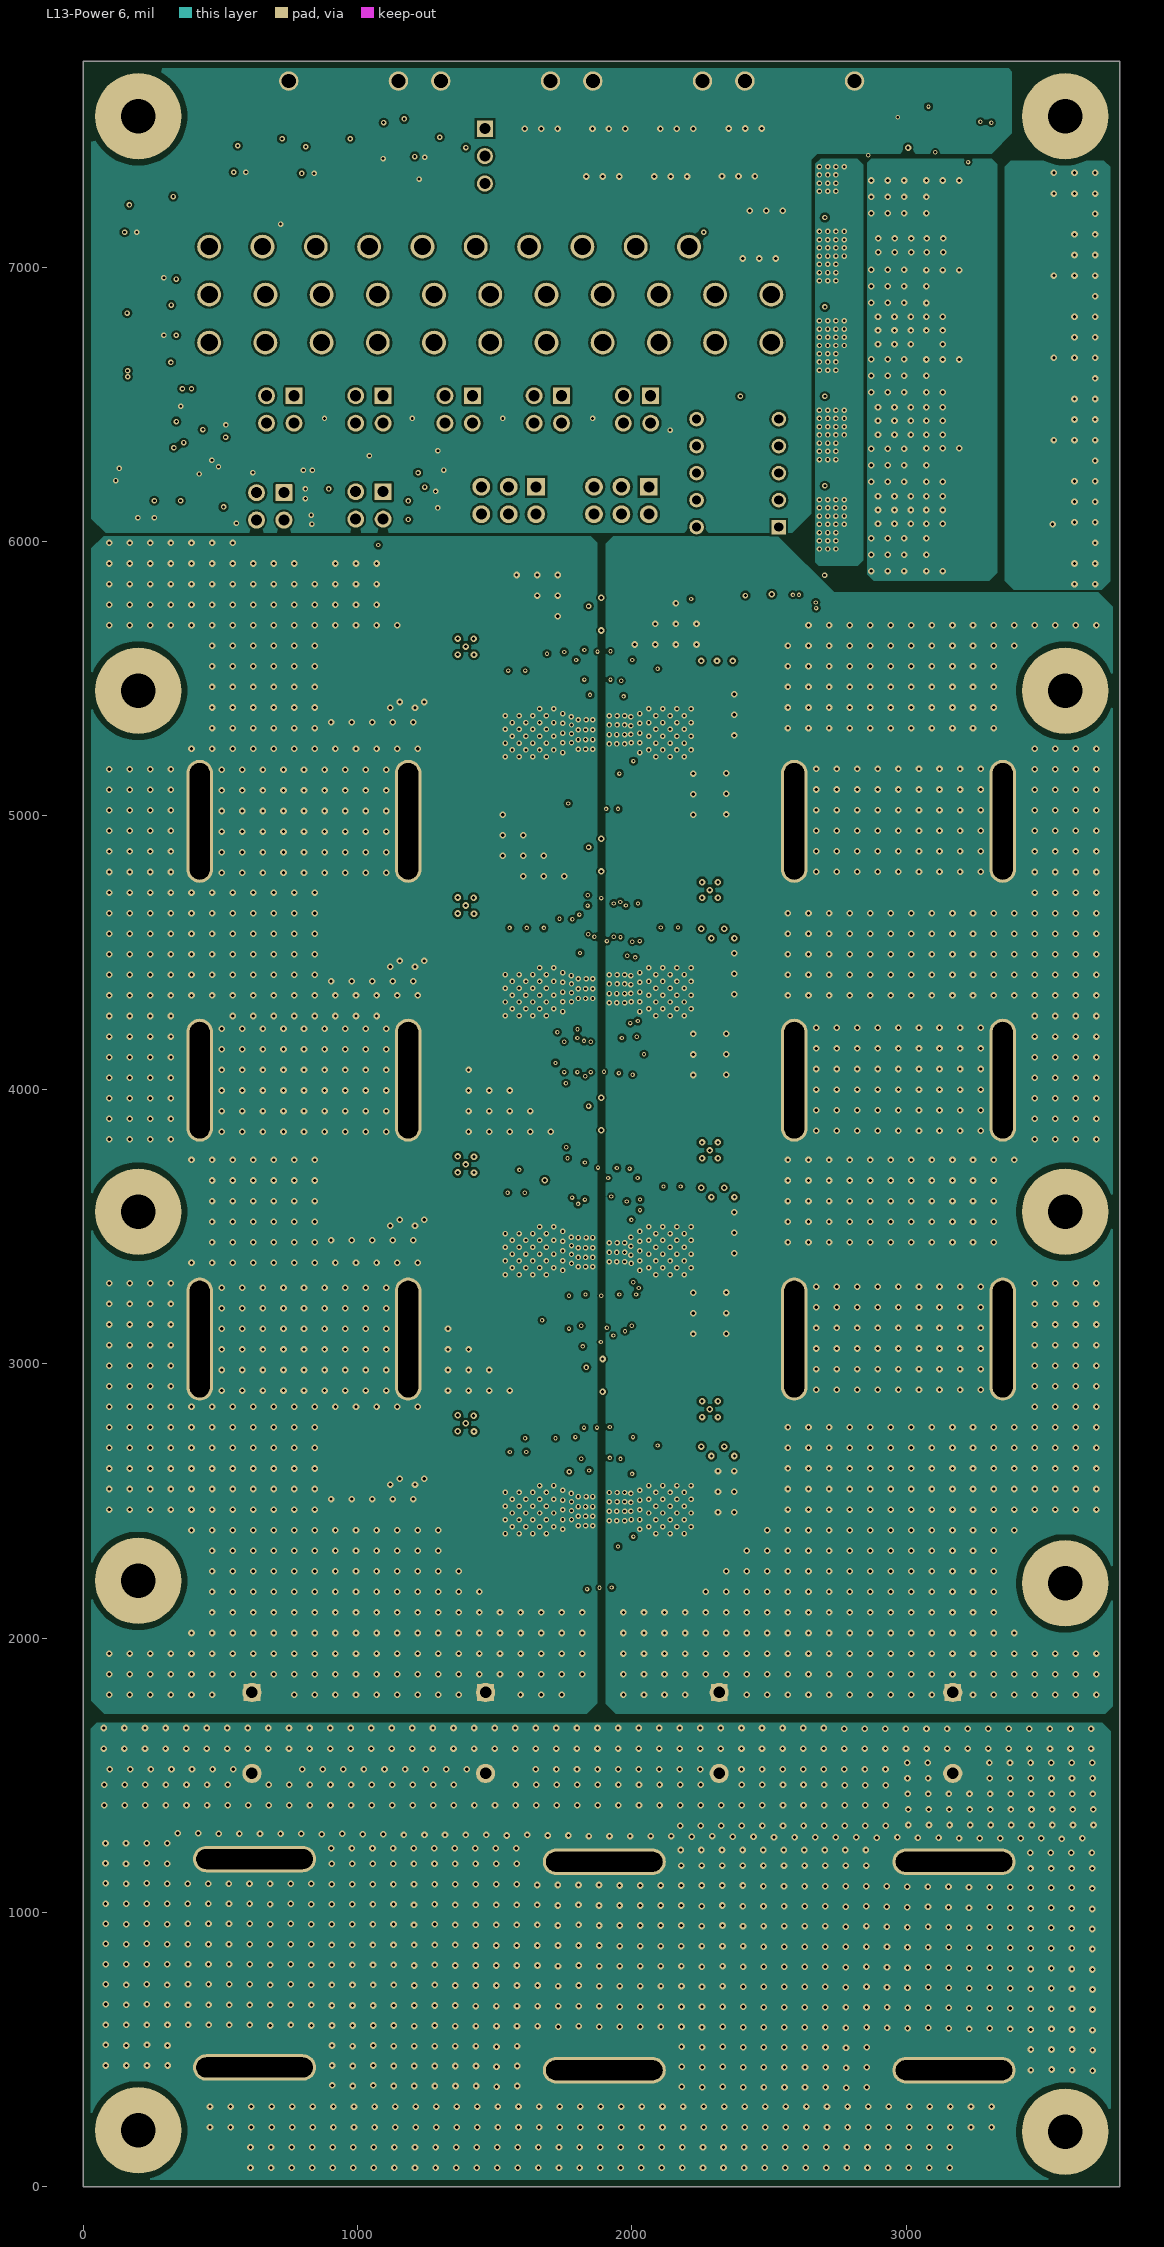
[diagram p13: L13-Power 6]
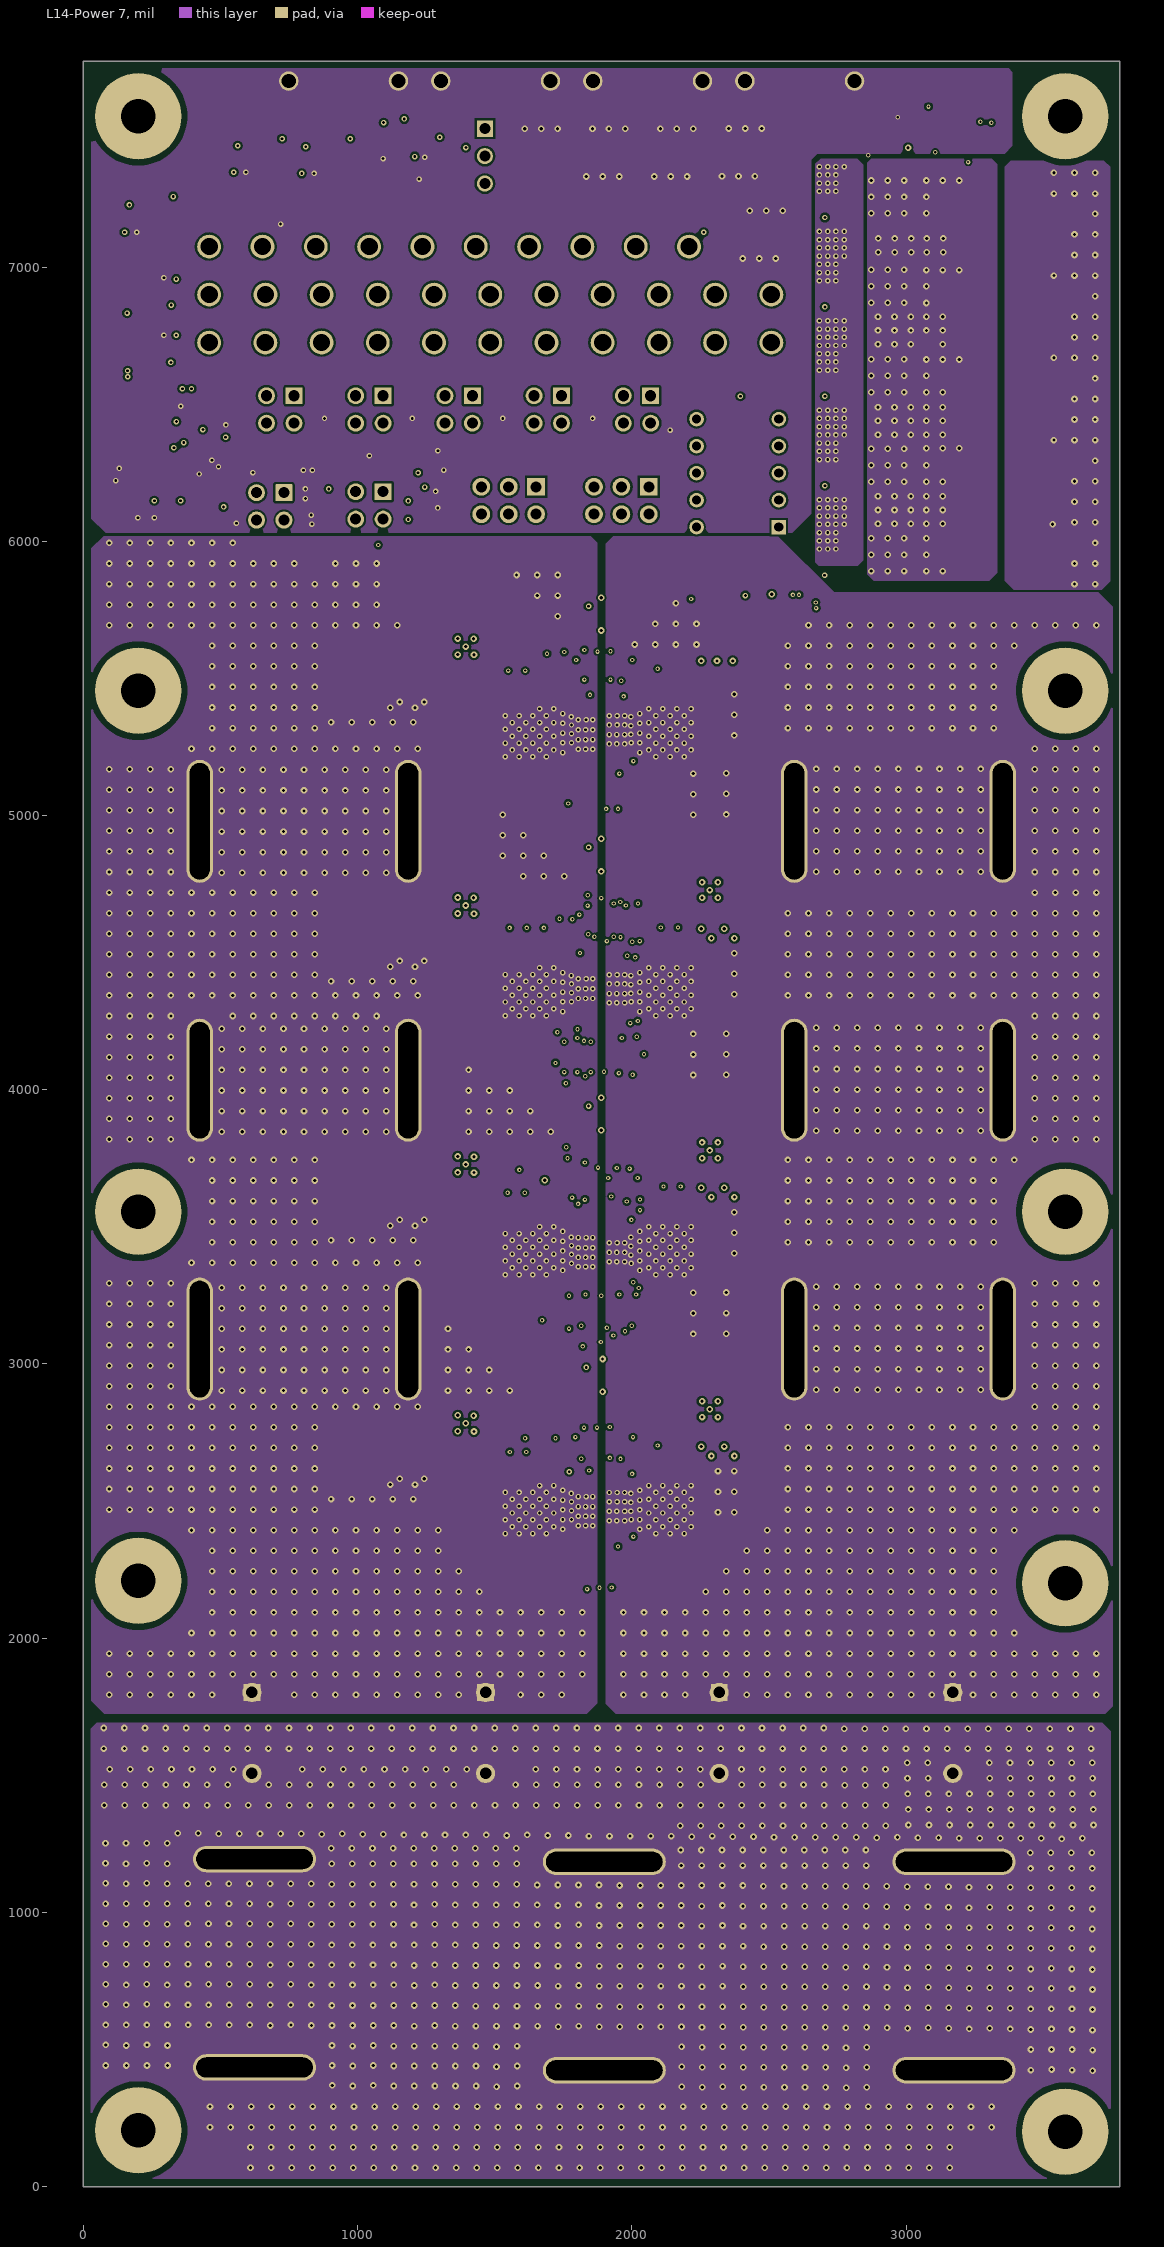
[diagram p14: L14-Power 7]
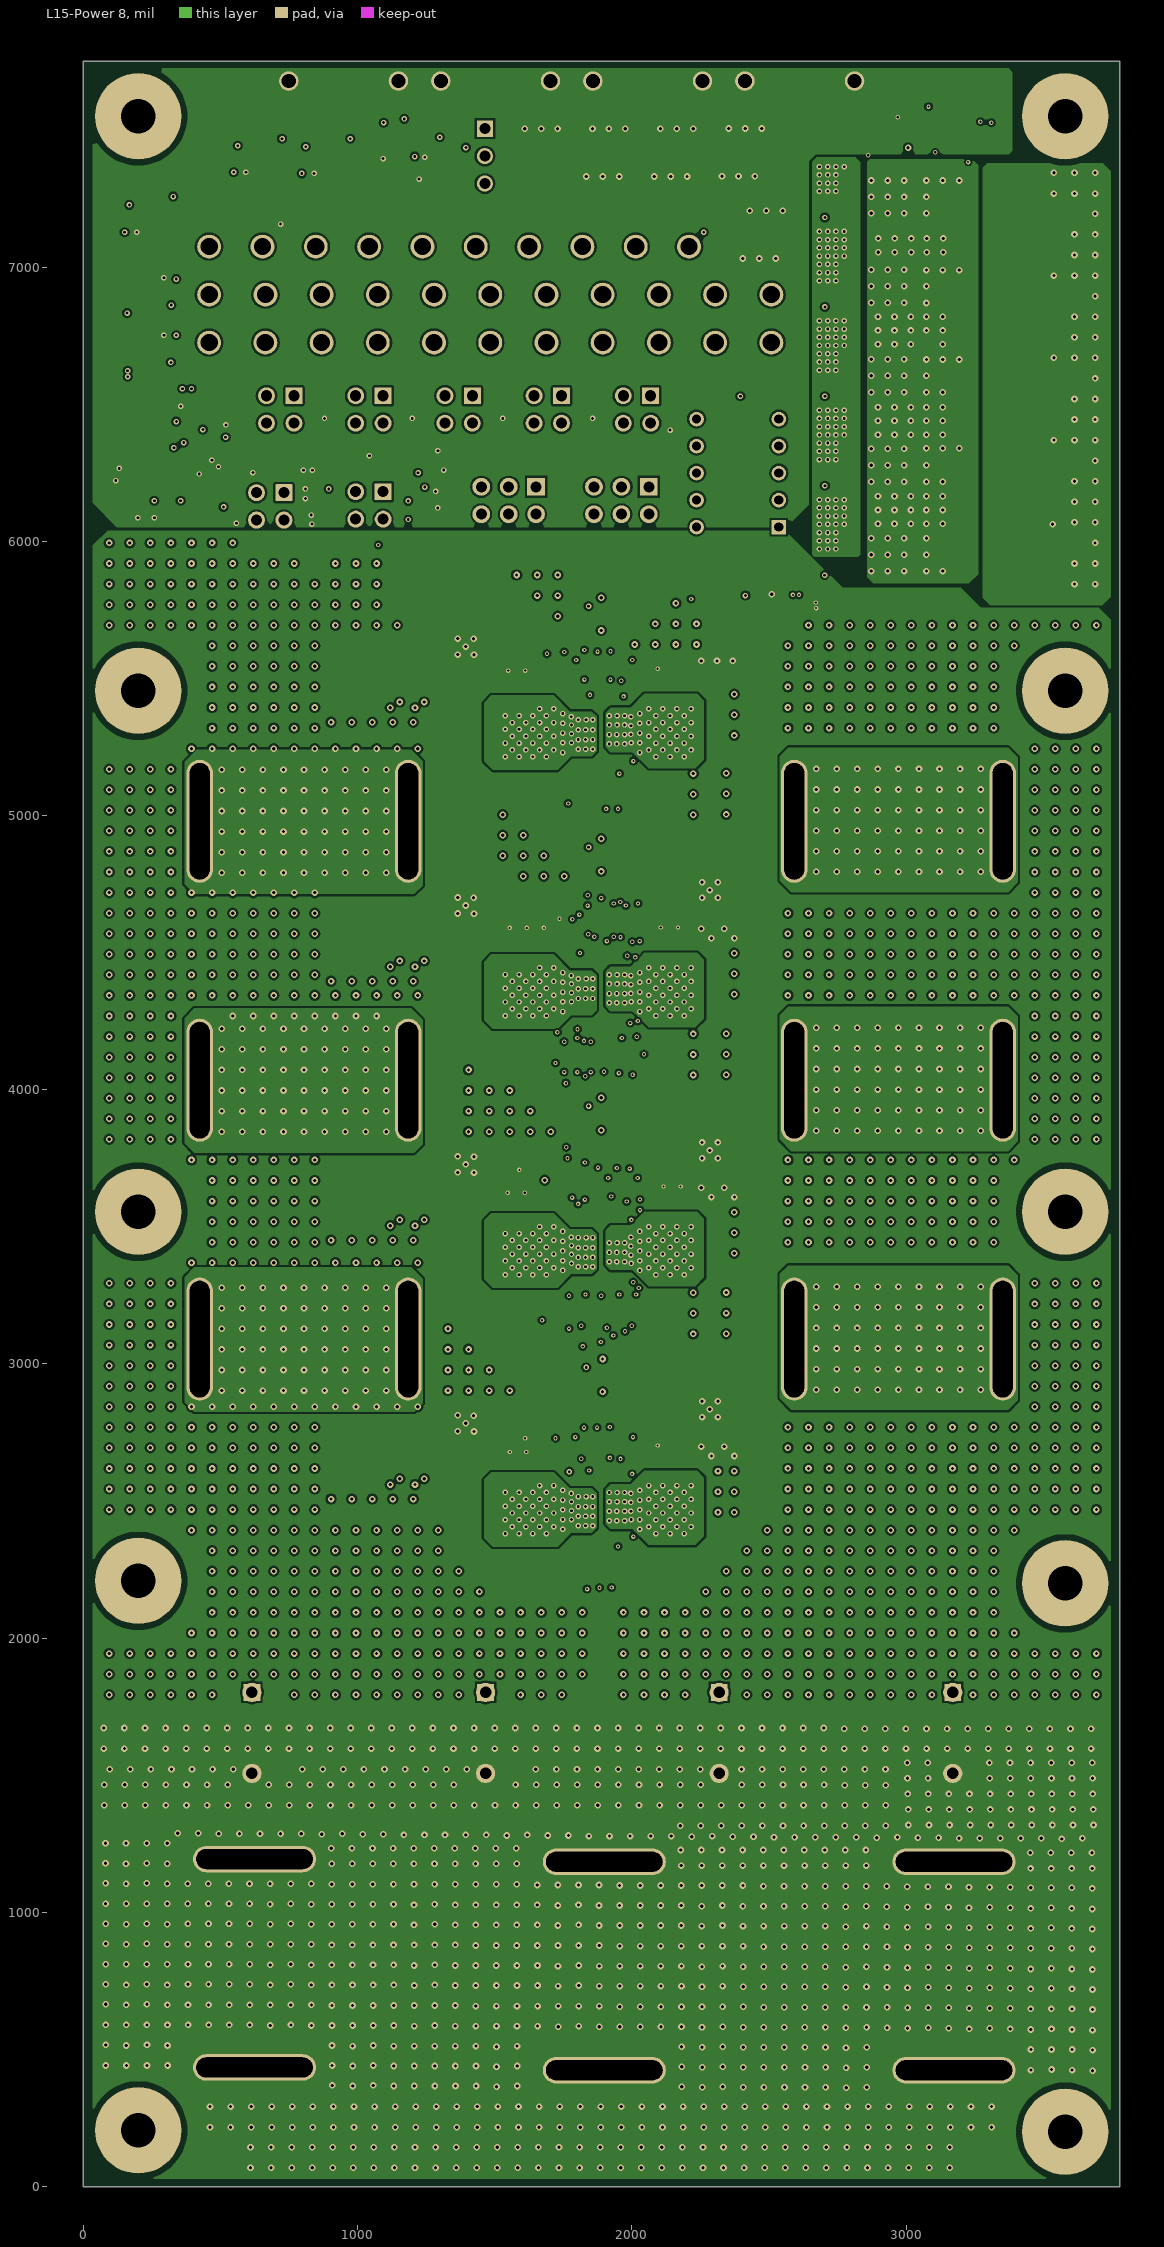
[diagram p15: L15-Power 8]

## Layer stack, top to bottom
Top Solder: solder mask 1, Solder Resist, Dk 3.5
Top Layer: signal copper 2.8
Dielectric 1: prepreg 5.486, FR-4 High TG, Dk 4.2
L2-Powet 1: signal copper 2.8
Dielectric 2: prepreg 5.118, FR-4 High TG, Dk 4.2
L3-Power 2: signal copper 2.8
Dielectric 3: dielectric 4.974, FR-4 High TG, Dk 4.2
L4-Power 3: signal copper 2.8
Dielectric 4: dielectric 5.118, FR-4 High TG, Dk 4.2
L5-Power 4: signal copper 2.8
Dielectric 5: prepreg 4.974, FR-4 High TG, Dk 4.2
L6-INT 1: signal copper 2.8
Dielectric 6: prepreg 5.118, FR-4 High TG, Dk 4.2
L7-INT 2: signal copper 2.8
Dielectric 7: dielectric 4.974, FR-4 High TG, Dk 4.2
L8-INT 3: signal copper 2.8
Dielectric 8: prepreg 5.118, FR-4 High TG, Dk 4.2
L9-INT 4: signal copper 2.8
Dielectric 9: dielectric 4.974, FR-4 High TG, Dk 4.2
L10-INT 5: signal copper 2.8
Dielectric 10: prepreg 5.118, FR-4 High TG, Dk 4.2
L11-INT 6: signal copper 2.8
Dielectric 11: prepreg 4.974, FR-4 High TG, Dk 4.2
L12-Power 5: signal copper 2.8
Dielectric 12: dielectric 5.118, FR-4 High TG, Dk 4.2
L13-Power 6: signal copper 2.8
Dielectric 13: dielectric 4.974, FR-4 High TG, Dk 4.2
L14-Power 7: signal copper 2.8
Dielectric 14: prepreg 5.118, FR-4 High TG, Dk 4.2
L15-Power 8: signal copper 2.8
Dielectric 15: prepreg 5.486, FR-4 High TG, Dk 4.2
Bottom Layer: signal copper 2.8
Bottom Solder: solder mask 1, Solder Resist, Dk 3.5

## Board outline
0,0 0,7750 3780,7750 3780,0

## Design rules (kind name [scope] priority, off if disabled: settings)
AcuteAngle [All] p1: minimum=4.50000000000000E+0001 checktracksonly=FALSE
AssemblyTestPointUsage [All] p1: valid=2
BoardOutlineClearance [All] p1: gap=10 ignorepadtopadclearanceinfootprint=FALSE except(0: Arc-SplitContinuation Track-SplitContinuation SMDPad-SplitContinuation THPad-SplitContinuation Via-SplitContinuation Fill-SplitContinuation Poly-SplitContinuation Region-SplitContinuation Text-SplitContinuation; 25: Poly-OutlineEdge Poly-CavityEdge Poly-CutoutEdge Poly-SplitBarrior)
Clearance Clearance_BoardEdge_MountingHoles [OnCopper and InComponentClass('Mounting Holes') vs IsKeepOut] p1: gap=40 ignorepadtopadclearanceinfootprint=FALSE except(0: Arc-Hole Track-Hole SMDPad-Hole THPad-Hole Via-Hole Fill-Hole Poly-Hole Region-Hole Text-Hole)
Clearance Clearance_BoardEdge_Poly [OnCopper and InPoly vs IsKeepOut] p2: gap=25 ignorepadtopadclearanceinfootprint=FALSE except(0: Arc-Hole Track-Hole SMDPad-Hole THPad-Hole Via-Hole Fill-Hole Poly-Hole Region-Hole Text-Hole)
Clearance Clearance_BoardEdge [OnCopper and Not InComponentClass('Logo') and not InComponentClass('FiducialMark') and not InRegion(1000,500,4000,800) and Not IsKeepout vs IsKeepOut] p3: gap=5 ignorepadtopadclearanceinfootprint=FALSE except(0: Arc-Hole Track-Hole SMDPad-Hole THPad-Hole Via-Hole Fill-Hole Poly-Hole Region-Hole Text-Hole)
Clearance Clearance_Poly [InPolygon] p4: gap=7.8 ignorepadtopadclearanceinfootprint=FALSE
Clearance [All] p5: gap=7.8 ignorepadtopadclearanceinfootprint=FALSE except(6: SMDPad-Via SMDPad-Region Via-Region Region-Region; 7: Arc-Arc Arc-Track Arc-SMDPad Track-Track Track-SMDPad Via-Hole)
ComponentClearance ComponentClearance_Logo [All] p1: gap=10 collisioncheckmode=3 verticalgap=10 showdistances=TRUE
ComponentClearance ComponentClearance_ScrewToNut [(HasFootprint('NY PMS 440 0025 PH')) vs (HasFootprint('Keystone_1902C'))] p2: gap=5 collisioncheckmode=3 verticalgap=10 showdistances=FALSE
ComponentClearance ComponentClearance_MountingHoles [InComponentClass('Mounting Holes')] p3: gap=10 collisioncheckmode=3 verticalgap=100000 showdistances=FALSE
ComponentClearance ComponentClearance_SmallPassives [HasFootprint('0201*') or HasFootprint('0402*') or HasFootprint('0508') or HasFootprint('0603*') or HasFootprint('0612') or HasFootprint('0805*') or HasFootprint('0815*') or HasFootprint('0830*') or HasFootprint('1206*') or HasFootprint('1210*') or HasFootprint('1808*') or HasFootprint('1812*') or HasFootprint('1825*') or HasFootprint('2010*') or HasFootprint('2220*') or HasFootprint('2225*') or HasFootprint('2512*') or HasFootprint('2728*') or HasFootprint('3518*') vs HasFootprint('0201*') or HasFootprint('0402*') or HasFootprint('0508') or HasFootprint('0603*') or HasFootprint('0612') or HasFootprint('0805*') or HasFootprint('0815*') or HasFootprint('0830*') or HasFootprint('1206*') or HasFootprint('1210*') or HasFootprint('1808*') or HasFootprint('1812*') or HasFootprint('1825*') or HasFootprint('2010*') or HasFootprint('2220*') or HasFootprint('2225*') or HasFootprint('2512*') or HasFootprint('2728*') or HasFootprint('3518*')] p4: gap=10 collisioncheckmode=3 verticalgap=10 showdistances=FALSE
ComponentClearance ComponentClearance_THtoSMT [IsThruComponent vs IsSMTComponent] p5: gap=10 collisioncheckmode=3 verticalgap=100000 showdistances=FALSE
ComponentClearance ComponentClearance_THtoTH [IsThruComponent vs IsThruComponent] p6: gap=10 collisioncheckmode=3 verticalgap=100000 showdistances=FALSE
ComponentClearance [All] p7: gap=10 collisioncheckmode=3 verticalgap=10 showdistances=FALSE
DiffPairsRouting DiffPair_DiffPairsRouting [All] p1: maxlimit=10 minlimit=10 mostfreqgap=10 toplayer_minwidth=10 toplayer_maxwidth=15 toplayer_prefwidth=10 midlayer1_minwidth=10 midlayer1_maxwidth=15 midlayer1_prefwidth=10 midlayer2_minwidth=10 midlayer2_maxwidth=15 midlayer2_prefwidth=10 midlayer3_minwidth=10 midlayer3_maxwidth=15 midlayer3_prefwidth=10 midlayer4_minwidth=10 midlayer4_maxwidth=15 midlayer4_prefwidth=10 midlayer5_minwidth=10 midlayer5_maxwidth=15 midlayer5_prefwidth=10 midlayer6_minwidth=15 midlayer6_maxwidth=15 midlayer6_prefwidth=15 midlayer7_minwidth=15 midlayer7_maxwidth=15 midlayer7_prefwidth=15 midlayer8_minwidth=15 midlayer8_maxwidth=15 midlayer8_prefwidth=15 midlayer9_minwidth=15 midlayer9_maxwidth=15 midlayer9_prefwidth=15 midlayer10_minwidth=15 midlayer10_maxwidth=15 midlayer10_prefwidth=15 midlayer11_minwidth=15 midlayer11_maxwidth=15 midlayer11_prefwidth=15 midlayer12_minwidth=15 midlayer12_maxwidth=15 midlayer12_prefwidth=15 midlayer13_minwidth=15 midlayer13_maxwidth=15 midlayer13_prefwidth=15 midlayer14_minwidth=15 midlayer14_maxwidth=15 midlayer14_prefwidth=15 bottomlayer_minwidth=15 bottomlayer_maxwidth=15 bottomlayer_prefwidth=15 maxuncoupledlength=500
DiffPairsRouting [All] p2: maxlimit=100 minlimit=10 mostfreqgap=10 toplayer_minwidth=15 toplayer_maxwidth=15 toplayer_prefwidth=15 midlayer1_minwidth=15 midlayer1_maxwidth=15 midlayer1_prefwidth=15 midlayer2_minwidth=15 midlayer2_maxwidth=15 midlayer2_prefwidth=15 midlayer3_minwidth=15 midlayer3_maxwidth=15 midlayer3_prefwidth=15 midlayer4_minwidth=15 midlayer4_maxwidth=15 midlayer4_prefwidth=15 midlayer5_minwidth=15 midlayer5_maxwidth=15 midlayer5_prefwidth=15 midlayer6_minwidth=15 midlayer6_maxwidth=15 midlayer6_prefwidth=15 midlayer7_minwidth=15 midlayer7_maxwidth=15 midlayer7_prefwidth=15 midlayer8_minwidth=15 midlayer8_maxwidth=15 midlayer8_prefwidth=15 midlayer9_minwidth=15 midlayer9_maxwidth=15 midlayer9_prefwidth=15 midlayer10_minwidth=15 midlayer10_maxwidth=15 midlayer10_prefwidth=15 midlayer11_minwidth=15 midlayer11_maxwidth=15 midlayer11_prefwidth=15 midlayer12_minwidth=15 midlayer12_maxwidth=15 midlayer12_prefwidth=15 midlayer13_minwidth=15 midlayer13_maxwidth=15 midlayer13_prefwidth=15 midlayer14_minwidth=15 midlayer14_maxwidth=15 midlayer14_prefwidth=15 bottomlayer_minwidth=15 bottomlayer_maxwidth=15 bottomlayer_prefwidth=15 maxuncoupledlength=1000
FabricationTestPointUsage TestPointUsage [All] p1: valid=2 allowmultiple=FALSE
FabricationTestpoint Testpoint [All] p1: side=3 testpointundercomponent=TRUE minsize=40 maxsize=100 preferedsize=60 minholesize=0 maxholesize=40 preferedholesize=32 testpointgrid=1 allowsidetop=TRUE allowsidebottom=TRUE usegrid=TRUE gridtolerance=0.01
FanoutControl Fanout_LCC [IsLCC] p1: bgadir=Out bgaviamode=Centered fanoutstyle=Auto fanoutdirection=Alternating viagrid=1 // Fanout_LCC (Default Rule)
FanoutControl Fanout_BGA [IsBGA] p2: bgadir=Out bgaviamode=Centered fanoutstyle=Auto fanoutdirection=Alternating viagrid=1 // Fanout_BGA (Default Rule)
FanoutControl Fanout_Default [All] p4: bgadir=Out bgaviamode=Centered fanoutstyle=Auto fanoutdirection=Alternating viagrid=1 // Fanout_Default (Default Rule)
FanoutControl Fanout_Small [(CompPinCount < 5)] p5: bgadir=Out bgaviamode=Centered fanoutstyle=Auto fanoutdirection=OutThenIn viagrid=1 // Fanout_Small (Default Rule)
HoleSize [All] p1: absolutevalues=TRUE maxlimit=475 minlimit=6 maxpercent=80.000 minpercent=20.000
MatchedLengths DiffPair_MatchedLengths [All] p1: tolerance=1000 checknetsindiffpair=FALSE checkdiffpairvsdiffpair=TRUE checkxsignals=TRUE checkothers=TRUE
MinimumAnnularRing [All] p1: minimumring=3
MinimumSolderMaskSliver MinimumSolderMaskSliver_Logo [InComponentClass('Logo') vs InComponentClass('Logo')] p1: minsoldermaskwidth=0.7
MinimumSolderMaskSliver [All] p2: minsoldermaskwidth=0
PlaneConnect [All] p1: planeconnectstyle=Direct reliefexpansion=10 reliefentries=4 reliefconductorwidth=10 reliefairgap=10
PolygonConnect [All] p1: connectstyle=Direct reliefconductorwidth=10 reliefentries=4 polygonreliefangle="90 Angle" airgapwidth=10
RoomDefinition TIDA-050077_DUT_2_3_4 [InComponentClass('TIDA-050077_DUT_2_3_4')] p1: confinementstyle=ConfineIn formatcopy=TRUE lockcomponents=FALSE outline -2275.87,-4972.46 -275.87,-4972.46 -275.87,-3972.46 -2275.87,-3972.46
RoomDefinition TIDA-050077_DUT_1 [InComponentClass('TIDA-050077_DUT_1')] p2: confinementstyle=ConfineIn formatcopy=TRUE lockcomponents=FALSE outline -2275.87,-4972.46 -275.87,-4972.46 -275.87,-3972.46 -2275.87,-3972.46
RoomDefinition TIDA-050077_HKeeping [InComponentClass('TIDA-050077_HKeeping')] p3: confinementstyle=ConfineIn formatcopy=TRUE lockcomponents=FALSE outline -2275.87,-4972.46 -275.87,-4972.46 -275.87,-3972.46 -2275.87,-3972.46
RoomDefinition TIDA-050077_Hardware [InComponentClass('TIDA-050077_Hardware')] p4: confinementstyle=ConfineIn formatcopy=TRUE lockcomponents=FALSE outline -2275.87,-4972.46 -275.87,-4972.46 -275.87,-3972.46 -2275.87,-3972.46
RoutingCorners [All] p1: cornerstyle=45-Degree minsetback=10 maxsetback=100
RoutingLayers [All] p1: top layer_v5=TRUE mid layer 1_v5=TRUE mid layer 2_v5=TRUE mid layer 3_v5=TRUE mid layer 4_v5=TRUE mid layer 5_v5=FALSE mid layer 6_v5=FALSE mid layer 7_v5=FALSE mid layer 8_v5=FALSE mid layer 9_v5=FALSE mid layer 10_v5=FALSE mid layer 11_v5=FALSE mid layer 12_v5=FALSE mid layer 13_v5=FALSE mid layer 14_v5=FALSE bottom layer_v5=TRUE
RoutingVias [All] p1: holewidth=16 width=34 viastyle="Through Hole" minholewidth=8 minwidth=16 maxholewidth=40 maxwidth=65
SMDToCorner [All] p1: distance=0
SilkToBoardRegionClearance [Not ((IsComment or IsDesignator) And (Hide <> 'False')) and not InRegion(1000,500,4000,800)] p1:
SilkToSilkClearance [All] p1: silktosilkclearance=0
SilkToSolderMaskClearance SilkscreenOverComponentPads [IsPad] p1: minsilkscreentomaskgap=0 clearancetoexposedcopper=TRUE
SolderMaskExpansion [All] p1: expansion=3 istentingtop=FALSE
Width [All] p1: maxlimit=100 minlimit=6 preferedwidth=10 checkconnectedcopper=TRUE
13 further rules are at their usual default settings.

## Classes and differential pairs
component class TIDA-050077_DUT_5_6: C61 C62 C63 C64 C65 C66 C67 C68 J9 J10 R73 R74 R75 R76 R77 R78 R79 R80 R81 R82 RM4 RM5 RZ33 RZ34 RZ35 RZ36 RZ37 RZ38 RZ39 RZ40 RZ41 RZ42 RZ43 RZ44 RZ45 RZ46 U5 U6
component class TIDA-050077_DUT_2_3_4: C49 C50 C51 C52 C53 C54 C55 C56 C57 C58 C59 C60 C93 J6 J7 J8 R55 R59 R60 R61 R62 R63 R64 R65 R66 R67 R68 R69 R70 R71 R72 RM1 RM2 RM3 RZ12 RZ13 RZ14 RZ15 RZ16 RZ17 RZ18 RZ19 RZ20 RZ21 RZ22 RZ23 RZ24 RZ25 RZ26 RZ27 RZ28 RZ29 RZ30 RZ31 RZ32 U2 U3 U4
component class TIDA-050077_HKeeping: C1 C2 C3 C4 C5 C6 C7 C8 C9 C10 C11 C12 C13 C14 C15 C16 C17 C18 CT1 DG1 DR1 DR2 DR3 DR4 DR5 DR6 G1 G2 G3 G4 J1 Q1 Q2 Q3 Q4 Q5 Q6 Q7 Q8 Q9 Q10 Q11 Q12 QGND1 QGND2 QGND3 QGND4 QGND5 R1 R2 R3 R4 R5 R6 R7 R8 R9 R10 R11 R12 R13 R14 R15 R16 R18 R19 R20 R21 R22 R23 R24 R25 R26 R27 R28 R29 R30 R31 R32 R33 R34 R35 R36 R37 R38 R39 R40 R52 R53 R56 R57 R58 R103 RZ1 RZ2 RZ3 RZ4 S1 SW3 TP1 TP2 TP3 TP4 TP5 TP6 TP7 TP8 TP15 TP23 TP24 U7 U8 U9 U10 U11 U12 U13 U14 U15 U16
component class TIDA-050077_DUT_1: C19 C20 C21 C22 C23 C24 C25 C26 C27 C28 C29 C30 C31 C32 C33 C34 C35 C36 C37 C38 C39 C40 C41 C42 C43 C44 C45 C46 C47 C48 CD1 CD2 CD3 CF1 CM1 CO1 CO2 CO3 CO4 CO5 CO6 CO7 CTEMP1 D1 D2 D3 D4 D5 D6 D7 D8 D9 D10 D11 D12 D13 J2 J3 J4 J5 R17 R41 R42 R43 R44 R45 R46 R47 R48 R49 R50 r51 R54 RL1 RL2 RZ5 RZ6 RZ7 RZ8 RZ9 RZ10 RZ11 RZ52 RZ53 RZ54 RZ55 RZ56 RZ57 SW1 SW2 T1 T2 T3 T4 T5 T6 T7 T8 T9 T10 T11 T12 T13 T14 T15 T16 T17 TP9 TP10 TP11 TP12 TP13 TP14 TP16 TP17 TP18 TP19 TP20 TP21 TP22 TP27 TP29 TP30 TP31 TP32 TP33 TP34 TP35 TP36 TP39 TP42 U1
component class TIDA-050077_Hardware: H1 H2 H3 H4 H5 H6 H7 H8 H9 H10 H11 H12 H13 H14 H15 H16 H17 H18 H19 H20 L1 L2 L3 L4 Logo1 SH1 SH2 SH3 SH4 SH5 SH6 SH7 SH8 SH9 ZZ1 ZZ2 ZZ3 ZZ4

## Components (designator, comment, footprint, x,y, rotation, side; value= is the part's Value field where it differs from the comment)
C1 "06035C104KAT2A" 0603 3005.07,7510.7 r270 top value=0.1uF
C2 "06035C104KAT2A" 0603 3182.57,7502.46 r270 top value=0.1uF
C3 "GRM1555C1H101JA01D" 0402 2915.26,7398.92 r180 top value=100pF
C4 "06035C104KAT2A" 0603 3179.79,7480.08 r180 bottom value=0.1uF
C5 "06035C104KAT2A" 0603 3179.79,7543.01 r180 bottom value=0.1uF
C6 "GCM188R71E105KA64D" 0603 2510.54,5838.63 r270 bottom value=1uF
C7 "GCM188R71E105KA64D" 0603 2514.33,5729.5 r180 top value=1uF
C8 "06035C104KAT2A" 0603 865,6017.04 r180 bottom value=0.1uF
C9 "06035C104KAT2A" 0603 863.21,6228.15 r180 bottom value=0.1uF
C10 "885012006057" 0603S 2728.33,6884.5 r270 top value=100pF
C11 "885012006057" 0603S 2728.33,7210.5 r270 top value=100pF
C12 "885012006057" 0603S 2728.33,6558.5 r270 top value=100pF
C13 "885012006057" 0603S 2728.33,6232.5 r270 top value=100pF
C14 "885012006057" 0603S 2728.33,5906.37 r270 top value=100pF
C15 "06035C104KAT2A" 0603 1272.53,6079.37 r0 top value=0.1uF
C16 "06035C104KAT2A" 0603 1266.04,6293.43 r0 top value=0.1uF
C17 "CL10B104KO8WPNC" 0603 1094.85,7457.98 r270 top value=0.1uF
C18 "885012006057" 0603 1192.75,7290.26 r180 top value=100pF
C19 "C1608X7R1V105K080AC" 0603 1616.81,4526.51 r90 top value=1uF
C20 "C0603C104K5RACAUTO" 0603 1679.34,4526.51 r90 top value=0.1uF
C21 "C1608X7R1V105K080AC" 0603 1554.28,4526.51 r90 top value=1uF
C22 "C0603C104K5RACAUTO" 0603 2105.75,4527.92 r90 bottom value=0.1uF
C23 "C1608X7R1V105K080AC" 0603 2105.75,4527.92 r90 top value=1uF
C24 "GRM188R6YA225KA12D" 0603 2168.28,4527.92 r90 top value=2.2uF
C25 "GRM188C71E225KE11D" 0603L 1783.34,4522.57 r90 top value=2.2uF
C26 "GRM1885C1H102JA01D" 0603 198.3,6205.3 r180 bottom value=1000pF
C27 "C0603C473J3RAC7867" FP-C0603C473J3RAC7867_0603-MFG 397.64,6190.3 r0 top value=47nF
C28 "GCJ188R71H223KA01D" FP-GCJ188R71H223KA01D_0603-MFG 1651,6333.69 r90 bottom value=22nF
C29 "GCJ188R71H333KA12D" FP-GCJ188R71H333KA12D_0603-MFG 1451,6333.69 r90 bottom value=33nF
C30 "GRM1885C1H332JA01D" 0603 1551,6348.69 r90 bottom value=3300pF
C31 "CKG57NX7S1E476M500JH" CKG57N 978.28,5456.05 r90 top value=47uF
C32 "CKG57NX7S1E476M500JH" CKG57N 978.28,4511.85 r90 top value=47uF
C33 "CKG57NX7S1E476M500JH" CKG57N 978.28,3567.66 r90 top value=47uF
C34 "C2012X5R1E106K125AB" 0805_HV 1226.71,5442.83 r90 top value=10uF
C35 "C2012X5R1E106K125AB" 0805_HV 1136.71,5442.83 r90 top value=10uF
C36 "C2012X5R1E106K125AB" 0805_HV 1226.71,4498.64 r90 top value=10uF
C37 "C2012X5R1E106K125AB" 0805_HV 1136.71,4498.64 r90 top value=10uF
C38 "C2012X5R1E106K125AB" 0805_HV 1226.71,3554.44 r90 top value=10uF
C39 "C2012X5R1E106K125AB" 0805_HV 1136.71,3554.44 r90 top value=10uF
C40 "CKG57NX7S1E476M500JH" CKG57N 978.28,3567.66 r90 bottom value=47uF
C41 "CKG57NX7S1E476M500JH" CKG57N 978.28,4511.85 r90 bottom value=47uF
C42 "CKG57NX7S1E476M500JH" CKG57N 978.28,2623.46 r90 top value=47uF
C43 "C2012X5R1E106K125AB" 0805_HV 1136.71,3554.44 r90 bottom value=10uF
C44 "C2012X5R1E106K125AB" 0805_HV 1226.71,3554.44 r90 bottom value=10uF
C45 "C2012X5R1E106K125AB" 0805_HV 1136.71,2610.25 r90 top value=10uF
C46 "C2012X5R1E106K125AB" 0805_HV 1226.71,2610.25 r90 top value=10uF
C47 "C2012X5R1E106K125AB" 0805_HV 1136.71,4498.64 r90 bottom value=10uF
C48 "C2012X5R1E106K125AB" 0805_HV 1226.71,4498.64 r90 bottom value=10uF
C49 "C1608X7R1V105K080AC" 0603 1549.28,5464.73 r90 top value=1uF
C50 "C0603C104K5RACAUTO" 0603 1611.52,5464.73 r90 top value=0.1uF
C51 "GRM188R6YA225KA12D" 0603 2094.18,5471.57 r90 top value=2.2uF
C52 "GRM188C71E225KE11D" 0603 1753.35,5525.9 r270 top value=2.2uF
C53 "C1608X7R1V105K080AC" 0603 1616.81,4526.51 r90 bottom value=1uF
C54 "C0603C104K5RACAUTO" 0603 1554.28,4526.51 r90 bottom value=0.1uF
C55 "GRM188R6YA225KA12D" 0603 2168.28,4527.92 r90 bottom value=2.2uF
C56 "GRM188C71E225KE11D" 0603 1695.95,4177.94 r90 top value=2.2uF
C57 "C1608X7R1V105K080AC" 0603 1609.26,3561.18 r90 bottom value=1uF
C58 "C0603C104K5RACAUTO" 0603 1609.26,3561.18 r90 top value=0.1uF
C59 "GRM188R6YA225KA12D" 0603 2115.7,3583.55 r90 top value=2.2uF
C60 "GRM188C71E225KE11D" 0603 1725.62,3638.15 r270 top value=2.2uF
C61 "C1608X7R1V105K080AC" 0603 1547.08,3561.18 r90 bottom value=1uF
C62 "C0603C104K5RACAUTO" 0603 1547.08,3561.18 r90 top value=0.1uF
C63 "GRM188R6YA225KA12D" 0603 2177.9,3583.55 r90 top value=2.2uF
C64 "GRM188C71E225KE11D" 0603 1717.14,3190.8 r90 bottom value=2.2uF
C65 "C1608X7R1V105K080AC" 0603 1555.44,2615.65 r90 top value=1uF
C66 "C0603C104K5RACAUTO" 0603 1615.01,2615.65 r90 top value=0.1uF
C67 "GRM188R6YA225KA12D" 0603 2094.18,2638.98 r90 top value=2.2uF
C68 "GRM188C71E225KE11D" 0603 1735.88,2638.06 r270 top value=2.2uF
CD1 "GCJ188R71H223KA01D" FP-GCJ188R71H223KA01D_0603-MFG 2057.47,6303.6 r90 bottom value=22nF
CD2 "GCJ188R71H333KA12D" FP-GCJ188R71H333KA12D_0603-MFG 1863.11,6307.1 r90 bottom value=33nF
CD3 "GRM1885C1H332JA01D" 0603 1961.46,6312.02 r90 bottom value=3300pF
CF1 "CGA2B2C0G1H102J050BA" 0402 679.55,7196.75 r0 top value=1000pF
CM1 "GCG1885G1H220JA01D" FP-GCG1885G1H220JA01D_0603-IPC_C 2019.86,4097.6 r180 bottom value=22pF
CO1 "EMVE250ADA471MJA0G" CAPSMT_62_JA0 2284.28,4903.17 r270 top value=470uF
CO2 "EMVE250ADA471MJA0G" CAPSMT_62_JA0 2284.28,3953.9 r270 top value=470uF
CO3 "EMVE250ADA471MJA0G" CAPSMT_62_JA0 2284.28,3009.7 r270 top value=470uF
CO4 "EKMQ250EIV472ML25S" KMQ_1600x2500 3170.31,1654.5 r270 top value=4700uF
CO5 "EKMQ250EIV472ML25S" KMQ_1600x2500 2318.45,1654.5 r270 top value=4700uF
CO6 "EKMQ250EIV472ML25S" KMQ_1600x2500 614.71,1654.5 r270 top value=4700uF
CO7 "EKMQ250EIV472ML25S" KMQ_1600x2500 1466.58,1654.5 r270 top value=4700uF
CT1 "C0603C104K5RACAUTO" 0603 1201.96,7506.72 r180 top value=0.1uF
CTEMP1 "06035A220JAT2A" 0603 1926.34,4023.9 r0 bottom value=22pF
D1 "BZX84-A4V7,215" FP-BZX84-A4V7,215_SOT23-3-MFG 453.39,6192.55 r180 bottom
D2 "5.0SMDJ12A" SMC 1393.92,3587.08 r90 top value=12V
D3 "5.0SMDJ12A" SMC 1393.92,5475.47 r90 top value=12V
D4 "5.0SMDJ12A" SMC 1393.92,3587.08 r90 bottom value=12V
D5 "5.0SMDJ12A" SMC 1393.92,4531.27 r90 top value=12V
D6 "5.0SMDJ12A" SMC 1393.92,2642.88 r90 top value=12V
D7 "5.0SMDJ12A" SMC 1393.92,4531.27 r90 bottom value=12V
D8 "PMEG045V100EPE-QZ" FP-PMEG045V100EPE-QZ_CFP15B-MFG 2314.28,2570.24 r0 top
D9 "PMEG045V100EPE-QZ" FP-PMEG045V100EPE-QZ_CFP15B-MFG 2314.28,5402.83 r0 top
D10 "PMEG045V100EPE-QZ" FP-PMEG045V100EPE-QZ_CFP15B-MFG 2314.28,4458.63 r180 bottom
D11 "PMEG045V100EPE-QZ" FP-PMEG045V100EPE-QZ_CFP15B-MFG 2314.28,4458.63 r0 top
D12 "PMEG045V100EPE-QZ" FP-PMEG045V100EPE-QZ_CFP15B-MFG 2314.28,3514.44 r180 bottom
D13 "PMEG045V100EPE-QZ" FP-PMEG045V100EPE-QZ_CFP15B-MFG 2314.28,3514.44 r0 top
DG1 "LG R971-KN-1" LG_R971_GREEN 178.48,6477.72 r90 top value=Green
DR1 "LS R976-NR-1" LS_R976_RED 562.48,6468.8 r90 top value=Red
DR2 "LS R976-NR-1" LS_R976_RED 249.43,6789.76 r180 top value=Red
DR3 "LS R976-NR-1" LS_R976_RED 249.43,7004.76 r180 top value=Red
DR4 "LS R976-NR-1" LS_R976_RED 240.14,7085.43 r0 top value=Red
DR5 "LS R976-NR-1" LS_R976_RED 636.98,7302.35 r0 top value=Red
DR6 "LS R976-NR-1" LS_R976_RED 884.99,7294.84 r0 top value=Red
FID5 "Fiducial" Fiducial10-20 475.9,7631.92 r315 top
FID5_1 "Fiducial" Fiducial10-20 3297.84,100.1 r315 top (schematic designator FID5)
FID5_2 "Fiducial" Fiducial10-20 445.07,94.18 r315 top (schematic designator FID5)
FID6 "Fiducial" Fiducial10-20 478.01,7636 r225 bottom
FID6_1 "Fiducial" Fiducial10-20 3299.94,104.18 r225 bottom (schematic designator FID6)
FID6_2 "Fiducial" Fiducial10-20 447.18,98.26 r225 bottom (schematic designator FID6)
G1 "D3082-05" Harwin_D3082-05 949,7678.25 r180 top
G2 "D3082-05" Harwin_D3082-05 1503.4,7678.25 r180 top
G3 "D3082-05" Harwin_D3082-05 2057.81,7678.25 r180 top
G4 "D3082-05" Harwin_D3082-05 2612.21,7678.25 r180 top
H1 "NY PMS 440 0025 PH" "NY PMS 440 0025 PH" 3580,7550 r0 top
H2 "NY PMS 440 0025 PH" "NY PMS 440 0025 PH" 200,7550 r0 top
H3 "NY PMS 440 0025 PH" "NY PMS 440 0025 PH" 3580,200 r0 top
H4 "NY PMS 440 0025 PH" "NY PMS 440 0025 PH" 200,205 r0 top
H5 "1902C" Keystone_1902C 3580.36,200 r180 bottom
H6 "1902C" Keystone_1902C 200.36,2208.9 r180 bottom
H7 "1902C" Keystone_1902C 200.36,205 r180 bottom
H8 "1902C" Keystone_1902C 3580.36,7550 r180 bottom
H9 "NY PMS 440 0025 PH" "NY PMS 440 0025 PH" 3580,3555 r0 top
H10 "NY PMS 440 0025 PH" "NY PMS 440 0025 PH" 200,3555 r0 top
H11 "NY PMS 440 0025 PH" "NY PMS 440 0025 PH" 200,2208.9 r0 top
H12 "NY PMS 440 0025 PH" "NY PMS 440 0025 PH" 3580,2200 r0 top
H13 "1902C" Keystone_1902C 3580.36,2200 r180 bottom
H14 "1902C" Keystone_1902C 3580.36,3555 r180 bottom
H15 "1902C" Keystone_1902C 3580.36,5455 r180 bottom
H16 "1902C" Keystone_1902C 200.36,5455 r180 bottom
H17 "NY PMS 440 0025 PH" "NY PMS 440 0025 PH" 200,5455 r0 top
H18 "NY PMS 440 0025 PH" "NY PMS 440 0025 PH" 3580,5455 r0 top
H19 "1902C" Keystone_1902C 200.36,7550 r180 bottom
H20 "1902C" Keystone_1902C 200.36,3555 r180 bottom
J1 "Header_3x1_Launchpad" CONN_PEC03SAAN 1464.28,7404.41 r270 top
J2 "PEC03DAAN" SULLINS_PEC03DAAN#1 1962.04,6148.69 r180 top
J3 "PEC02DABN" FP-PEC02DABN_HDR4-MFG 1043.21,6130.62 r180 top
J4 "PEC02DABN" FP-PEC02DABN_HDR4-MFG 681.41,6127.18 r180 top
J5 "PEC03DAAN" SULLINS_PEC03DAAN#2 1551,6148.69 r180 top
J6 "PEC02DABN" FP-PEC02DABN_HDR4-MFG 717.98,6480.62 r180 top
J7 "PEC02DABN" FP-PEC02DABN_HDR4-MFG 1043.21,6480.62 r180 top
J8 "PEC02DABN" FP-PEC02DABN_HDR4-MFG 1693.66,6480.62 r180 top
J9 "PEC02DABN" FP-PEC02DABN_HDR4-MFG 1368.43,6480.62 r180 top
J10 "PEC02DABN" FP-PEC02DABN_HDR4-MFG 2018.88,6480.62 r180 top
L1 "WEEE logo" WEEE_Minimum 901.22,2246.09 r0 top
L2 "FCC disclaimer" FCC_disclaimer 4779.13,4772.54 r90 top
L3 "CAUTION HOT SURFACE" IEC_HotSurface_Small 621.46,2229.32 r0 top
L4 "CE Mark" CE_Mark_5mm 1221.22,2216.09 r0 top
Logo1 "Texas Instruments" TI_Stacked_Overlay_Small 2973.8,2658.14 r0 top
Q1 "SI2306BDS-T1-GE3" FP-SI2306BDS-T1-GE3_SOT23-3-MFG 281.08,6454.76 r180 top
Q2 "SI2306BDS-T1-GE3" FP-SI2306BDS-T1-GE3_SOT23-3-MFG 457.59,6462.5 r90 top
Q3 "SI2306BDS-T1-GE3" FP-SI2306BDS-T1-GE3_SOT23-3-MFG 254.95,6689.76 r180 top
Q4 "SI2306BDS-T1-GE3" FP-SI2306BDS-T1-GE3_SOT23-3-MFG 254.95,6897.26 r180 top
Q5 "SI2306BDS-T1-GE3" FP-SI2306BDS-T1-GE3_SOT23-3-MFG 233.66,7189.27 r0 top
Q6 "SI2306BDS-T1-GE3" FP-SI2306BDS-T1-GE3_SOT23-3-MFG 631.46,7404.33 r0 top
Q7 "SI2306BDS-T1-GE3" FP-SI2306BDS-T1-GE3_SOT23-3-MFG 879.47,7401.46 r0 top
Q8 "CSD18510Q5B" DNK0008A 2890.23,6929.56 r0 top value=40V
Q9 "CSD18510Q5B" DNK0008A 2890.23,7255.62 r0 top value=40V
Q10 "CSD18510Q5B" DNK0008A 2890.23,6603.5 r0 top value=40V
Q11 "CSD18510Q5B" DNK0008A 2890.23,6277.43 r0 top value=40V
Q12 "CSD18510Q5B" DNK0008A 2890.23,5951.37 r0 top value=40V
QGND1 "5016" Testpoint_Keystone_Compact 2460.41,7120.01 r180 top
QGND2 "5016" Testpoint_Keystone_Compact 1668.81,7415.84 r0 top
QGND3 "5016" Testpoint_Keystone_Compact 1918.81,7415.84 r0 top
QGND4 "5016" Testpoint_Keystone_Compact 2168.81,7415.84 r0 top
QGND5 "5016" Testpoint_Keystone_Compact 2418.45,7416.39 r0 top
R1 "RC0603JR-07470RL" 0603 162.04,6898.26 r90 top value=470
R2 "RC0603JR-07470RL" 0603 326.57,7190.43 r270 top value=470
R3 "RC0603JR-07470RL" 0603 724.38,7402.68 r270 top value=470
R4 "RC0603JR-07470RL" 0603 972.38,7401.46 r270 top value=470
R5 "RC0402FR-0710KL" 0402 338.47,6692.26 r270 top value=10.0k
R6 "RC0402FR-0710KL" 0402 338.47,6897.37 r270 top value=10.0k
R7 "RC0603JR-07470RL" 0603 162.04,6689.76 r90 top value=470
R8 "RC0603JR-07470RL" 0603 293.48,6556.56 r0 top value=470
R9 "RC0603JR-07470RL" 0603 461.08,6556.19 r0 top value=470
R10 "RC0402FR-0710KL" 0402 150.14,7185.43 r90 top value=10.0k
R11 "RC0402FR-0710KL" 0402 547.94,7404.41 r90 top value=10.0k
R12 "RC0402FR-0710KL" 0402 795.95,7400.25 r90 top value=10.0k
R13 "RC0603FR-0710KL" 0603 3053.27,7480.73 r180 bottom value=10.0k
R14 "RC0603FR-0710KL" 0603 3053.27,7543.4 r180 bottom value=10.0k
R15 "CR160000F" FP-CR160000F_0603-MFG 3164.53,7399.47 r180 top value=0
R16 "CR160000F" FP-CR160000F_0603-MFG 3024.73,7600.87 r0 top value=0
R17 "CRCW0402330KFKED" 0402 204.02,6265.6 r0 bottom value=330k
R18 "RC0603JR-0710RL" FP-RC0603JR-0710RL_0603-MFG 2662.29,6885.07 r0 bottom value=10
R19 "RC0603JR-0710RL" FP-RC0603JR-0710RL_0603-MFG 2660.32,7210.5 r0 bottom value=10
R20 "RC0603JR-0710RL" FP-RC0603JR-0710RL_0603-MFG 2663.09,6557.06 r0 bottom value=10
R21 "RC0603JR-0710RL" FP-RC0603JR-0710RL_0603-MFG 2661.19,6230.06 r0 bottom value=10
R22 "RC0603JR-0710RL" FP-RC0603JR-0710RL_0603-MFG 2625.53,5935.11 r0 bottom value=10
R23 "SMW5R51JT" FP-SMW51R0JT_5329-IPC_C 3388.22,6289.5 r0 top value=1
R24 "SMW5R51JT" FP-SMW51R0JT_5329-IPC_C 3388.22,5976.37 r0 top value=1
R25 "SMW5R51JT" FP-SMW51R0JT_5329-IPC_C 3386.33,6603.5 r0 top value=1
R26 "SMW5R51JT" FP-SMW51R0JT_5329-IPC_C 3388.03,7221.95 r0 top value=1
R27 "SMW5R51JT" FP-SMW51R0JT_5329-IPC_C 3388.03,6911.95 r0 top value=1
R28 "CSS2H-3920R-1L00F" FP-CSS2H-3920R-1L00F_3920-MFG 3369.16,6828.44 r0 bottom value=1m
R29 "CSS2H-3920R-1L00F" FP-CSS2H-3920R-1L00F_3920-MFG 3369.16,6512.12 r0 bottom value=1m
R30 "CSS2H-3920R-1L00F" FP-CSS2H-3920R-1L00F_3920-MFG 3369.16,6200.81 r0 bottom value=1m
R31 "CSS2H-3920R-1L00F" FP-CSS2H-3920R-1L00F_3920-MFG 3369.16,5879.5 r0 bottom value=1m
R32 "CSS2H-3920R-1L00F" FP-CSS2H-3920R-1L00F_3920-MFG 3369.16,7144.75 r0 bottom value=1m
R33 "RC0603JR-0710RL" FP-RC0603JR-0710RL_0603-MFG 2644.33,6856.72 r0 top value=10
R34 "RC0603JR-0710RL" FP-RC0603JR-0710RL_0603-MFG 2644.33,7183.5 r0 top value=10
R35 "RC0603JR-0710RL" FP-RC0603JR-0710RL_0603-MFG 2644.33,6529.93 r0 top value=10
R36 "RC0603JR-0710RL" FP-RC0603JR-0710RL_0603-MFG 2644.33,6203.15 r0 top value=10
R37 "RC0603JR-0710RL" FP-RC0603JR-0710RL_0603-MFG 2644.33,5876.37 r0 top value=10
R38 "RC0603JR-0710KL" 0603 1094.85,7322.98 r270 top value=10k
R39 "RC0603JR-0710KL" 0603 1328.45,7436.72 r0 top value=10k
R40 "RC0603JR-0710KL" 0603 1192.75,7351.34 r0 top value=10k
R41 "RC0603JR-0710RL" FP-RC0603JR-0710RL_0603-MFG 1712.81,4495.01 r0 bottom value=10
R42 "CRCW04021M00JNED" 0402L 292.74,6240.3 r90 bottom value=1.0Meg
R43 "RC0402FR-0710KL" 0402 459.71,6379.76 r180 top value=10.0k
R44 "RC0402FR-0710KL" 0402 366.08,6421.27 r90 top value=10.0k
R45 "RT0603BRD0740K2L" 0603 687.43,7196.75 r180 bottom value=40.2k
R46 "CRCW060310K0FKEA" 0603 354.41,6221.5 r270 bottom value=10.0k
R47 "RC0402FR-0710KL" 0402 1978.24,4615.13 r270 top value=10.0k
R48 "RC0603FR-07121KL" 0603 395.52,6295.3 r0 top value=121k
R49 "CRCW0402100KFKED" 0402 437.64,6125.9 r180 top value=100k
R50 "RC0402FR-0710KL" 0402 1839.01,4615.01 r270 top value=10.0k
r51 "RT0603BRD07167RL" 0603 1093.21,6280.62 r270 bottom value=167 (schematic designator R51)
R52 "CRCW060310K0FKEA" 0603 2430.23,6051.59 r0 bottom value=10.0k
R53 "CRCW060320K0FKEA" 0603 2430.23,6150.84 r0 bottom value=20.0k
R54 "RT0603BRD07249RL" 0603 993.21,6280.62 r270 bottom value=249
R55 "RC0402FR-0710KL" 0402 1922.32,5543.42 r270 top value=10.0k
R56 "CRCW060349K9FKEA" 0603 2430.23,6250.84 r0 bottom value=49.9k
R57 "CRCW0603100KFKEA" 0603 2430.23,6345.84 r0 bottom value=100k
R58 "CRCW0603200KFKEA" 0603 2430.23,6445.84 r0 bottom value=200k
R59 "RC0603JR-0710RL" FP-RC0603JR-0710RL_0603-MFG 1686.42,5471.3 r270 top value=10
R60 "RC0402FR-0710KL" 0402 1827.2,5543.42 r270 top value=10.0k
R61 "RT0603BRD07365RL" 0603 844.33,6479.5 r90 bottom value=365
R62 "RT0603BRD07464RL" 0603 604.33,6479.5 r90 bottom value=464
R63 "RC0402FR-0710KL" 0402 1850.05,4121.22 r90 top value=10.0k
R64 "RC0603JR-0710RL" FP-RC0603JR-0710RL_0603-MFG 1695.95,4242.9 r90 bottom value=10
R65 "RC0402FR-0710KL" 0402 1753.27,4121.22 r90 bottom value=10.0k
R66 "RT0603BRD07365RL" 0603 1164.33,6479.5 r90 bottom value=365
R67 "RT0603BRD07464RL" 0603 919.33,6479.5 r90 bottom value=464
R68 "RC0402FR-0710KL" 0402 1945.62,3654.65 r270 bottom value=10.0k
R69 "RC0603JR-0710RL" FP-RC0603JR-0710RL_0603-MFG 1714.6,3543.27 r180 top value=10
R70 "RC0402FR-0710KL" 0402 1781.34,3654.65 r270 top value=10.0k
R71 "RT0603BRD07365RL" 0603 1814.81,6479.5 r90 bottom value=365
R72 "RT0603BRD07464RL" 0603 1569.33,6479.5 r90 bottom value=464
R73 "RC0402FR-0710KL" 0402 1909.19,3190.9 r90 top value=10.0k
R74 "RC0603JR-0710RL" FP-RC0603JR-0710RL_0603-MFG 1683.67,3273.9 r180 bottom value=10
R75 "RC0402FR-0710KL" 0402 1770.85,3190.9 r90 top value=10.0k
R76 "RT0603BRD07365RL" 0603 1486.82,6482 r90 bottom value=365
R77 "RT0603BRD07464RL" 0603 1244.33,6479.5 r90 bottom value=464
R78 "RC0402FR-0710KL" 0402 1920.13,2709.45 r270 top value=10.0k
R79 "RC0603JR-0710RL" FP-RC0603JR-0710RL_0603-MFG 1702.42,2606.56 r180 bottom value=10
R80 "RC0402FR-0710KL" 0402 1825.64,2709.45 r270 top value=10.0k
R81 "RT0603BRD07365RL" 0603 2139.33,6479.5 r90 bottom value=365
R82 "RT0603BRD07464RL" 0603 1898.82,6479.5 r90 bottom value=464
RL1 "RT0603BRD07365RL" 0603 691.71,6253.15 r0 bottom value=365
RL2 "RT0603BRD07464RL" 0603 558.21,6145.69 r90 bottom value=464
RM1 "CRCW04020000Z0ED" 0402 1969.88,5543.42 r90 top value=0
RM2 "CRCW04020000Z0ED" 0402 1946.84,4121.22 r270 bottom value=0
RM3 "CRCW04020000Z0ED" 0402 1991.91,3654.65 r90 top value=0
RM4 "CRCW04020000Z0ED" 0402 1954.58,3190.9 r270 bottom value=0
RM5 "CRCW04020000Z0ED" 0402 1966.85,2709.45 r90 top value=0
RZ1 "CRCW04020000Z0ED" 0402 3237.75,7447.47 r90 top value=0
RZ2 "CRCW04020000Z0ED" 0402 3018.2,7398.92 r0 top value=0
RZ3 "CRCW04020000Z0ED" 0402 3236.8,7553.56 r270 top value=0
RZ4 "CRCW04020000Z0ED" 0402 1321.96,7511.72 r0 top value=0
RZ5 "CRCW04020000Z0ED" 0402 1759.72,4591.62 r180 top value=0
RZ6 "CRCW04020000Z0ED" 0402 1978.24,4615.13 r90 bottom value=0
RZ7 "CRCW04020000Z0ED" 0402 1801.66,4121.22 r270 top value=0
RZ8 "CRCW04020000Z0ED" 0402 1898.45,4121.22 r270 top value=0
RZ9 "CRCW04020000Z0ED" 0402 1839.01,4615.01 r90 bottom value=0
RZ10 "CRCW04020000Z0ED" 0402 1934.13,4615.01 r90 top value=0
RZ11 "CRCW04020000Z0ED" 0402 1995.23,4121.22 r270 top value=0
RZ12 "CRCW04020000Z0ED" 0402 1922.32,5543.42 r90 bottom value=0
RZ13 "CRCW04020000Z0ED" 0402 1666.87,5559.9 r180 top value=0
RZ14 "CRCW04020000Z0ED" 0402 1862.98,5078.36 r270 top value=0
RZ15 "CRCW04020000Z0ED" 0402 1906.22,5078.36 r270 top value=0
RZ16 "CRCW04020000Z0ED" 0402 1827.2,5543.42 r90 bottom value=0
RZ17 "CRCW04020000Z0ED" 0402 1874.76,5543.42 r90 top value=0
RZ18 "CRCW04020000Z0ED" 0402 1949.46,5078.36 r270 top value=0
RZ19 "CRCW04020000Z0ED" 0402 1850.05,4121.22 r270 bottom value=0
RZ20 "CRCW04020000Z0ED" 0402 1759.72,4591.62 r180 bottom value=0
RZ21 "CRCW04020000Z0ED" 0402 1886.57,4615.01 r90 bottom value=0
RZ22 "CRCW04020000Z0ED" 0402 1934.13,4615.01 r90 bottom value=0
RZ23 "CRCW04020000Z0ED" 0402 1753.27,4121.22 r270 top value=0
RZ24 "CRCW04020000Z0ED" 0402 1801.66,4121.22 r270 bottom value=0
RZ25 "CRCW04020000Z0ED" 0402 2022.34,4615.24 r90 bottom value=0
RZ26 "CRCW04020000Z0ED" 0402 1945.62,3654.65 r90 top value=0
RZ27 "CRCW04020000Z0ED" 0402 1645.46,3707.77 r180 top value=0
RZ28 "CRCW04020000Z0ED" 0402 1862.98,3190.9 r270 top value=0
RZ29 "CRCW04020000Z0ED" 0402 1954.58,3190.9 r270 top value=0
RZ30 "CRCW04020000Z0ED" 0402 1781.34,3654.65 r90 bottom value=0
RZ31 "CRCW04020000Z0ED" 0402 1828.77,3654.65 r90 top value=0
RZ32 "CRCW04020000Z0ED" 0402 1999.97,3190.9 r270 top value=0
RZ33 "CRCW04020000Z0ED" 0402 1909.19,3190.9 r270 bottom value=0
RZ34 "CRCW04020000Z0ED" 0402 1645.46,3707.77 r180 bottom value=0
RZ35 "CRCW04020000Z0ED" 0402 1828.77,3654.65 r90 bottom value=0
RZ36 "CRCW04020000Z0ED" 0402 1876.59,3654.65 r90 bottom value=0
RZ37 "CRCW04020000Z0ED" 0402 1770.85,3190.9 r270 bottom value=0
RZ38 "CRCW04020000Z0ED" 0402 1816.55,3190.9 r270 bottom value=0
RZ39 "CRCW04020000Z0ED" 0402 1991.91,3654.65 r90 bottom value=0
RZ40 "CRCW04020000Z0ED" 0402 1920.13,2709.45 r90 bottom value=0
RZ41 "CRCW04020000Z0ED" 0402 1666.32,2728.9 r180 top value=0
RZ42 "CRCW04020000Z0ED" 0402 1835.88,2239.73 r270 top value=0
RZ43 "CRCW04020000Z0ED" 0402 1882.14,2239.73 r270 top value=0
RZ44 "CRCW04020000Z0ED" 0402 1825.64,2709.45 r90 bottom value=0
RZ45 "CRCW04020000Z0ED" 0402 1872.89,2709.45 r90 top value=0
RZ46 "CRCW04020000Z0ED" 0402 1926.37,2239.73 r270 top value=0
S1 "76SB05ST" SW_76SB05 2385.98,6248.44 r180 top
SH1 "60900213621" Wurth_60900213621 762.16,6492.26 r90 top
SH2 "60900213621" Wurth_60900213621 1088.52,6482 r90 top
SH3 "60900213621" Wurth_60900213621 733.53,6130.62 r90 top
SH4 "60900213621" Wurth_60900213621 1096.83,6131.19 r90 top
SH5 "60900213621" Wurth_60900213621 1409.3,6482 r90 top
SH6 "60900213621" Wurth_60900213621 1743.66,6482 r90 top
SH7 "60900213621" Wurth_60900213621 1651,6148.69 r90 top
SH8 "60900213621" Wurth_60900213621 2062.04,6148.69 r90 top
SH9 "60900213621" Wurth_60900213621 2066.92,6482 r90 top
SW1 "PTS830GM140SMTRLFS" FP-PTS830GM140SMTRLFS_SMT_3MM05_2MM6-MFG 231.03,6115.09 r180 top
SW2 "PTS830GM140SMTRLFS" FP-PTS830GM140SMTRLFS_SMT_3MM05_2MM6-MFG 229.02,6250.3 r0 top
SW3 "PTS830GM140SMTRLFS" FP-PTS830GM140SMTRLFS_SMT_3MM05_2MM6-MFG 1326.96,7316.72 r90 top
T1 "Turret" "CONN_ 0300-2-15-01-47-01-10-0" 2318.45,1802.14 r0 top
T2 "Turret" "CONN_ 0300-2-15-01-47-01-10-0" 3170.31,1802.14 r0 top
T3 "Turret" "CONN_ 0300-2-15-01-47-01-10-0" 2318.45,1506.87 r0 top
T4 "Turret" "CONN_ 0300-2-15-01-47-01-10-0" 3170.31,1506.87 r0 top
T5 "B1/0-PCB-L" FP-B1-0-PCB-L_WIRE_LUG_150A_1-0AWG-MFG 804.28,4034.7 r180 top
T6 "B1/0-PCB-L" FP-B1-0-PCB-L_WIRE_LUG_150A_1-0AWG-MFG 804.28,3090.51 r180 top
T7 "B1/0-PCB-L" FP-B1-0-PCB-L_WIRE_LUG_150A_1-0AWG-MFG 804.28,4978.9 r180 top
T8 "B1/0-PCB-L" FP-B1-0-PCB-L_WIRE_LUG_150A_1-0AWG-MFG 2972.49,4978.9 r0 top
T9 "B1/0-PCB-L" FP-B1-0-PCB-L_WIRE_LUG_150A_1-0AWG-MFG 2972.49,4034.7 r180 top
T10 "B1/0-PCB-L" FP-B1-0-PCB-L_WIRE_LUG_150A_1-0AWG-MFG 2972.49,3090.51 r180 top
T11 "B1/0-PCB-L" FP-B1-0-PCB-L_WIRE_LUG_150A_1-0AWG-MFG 624.28,814.5 r90 top
T12 "B1/0-PCB-L" FP-B1-0-PCB-L_WIRE_LUG_150A_1-0AWG-MFG 1899.58,804.5 r90 top
T13 "B1/0-PCB-L" FP-B1-0-PCB-L_WIRE_LUG_150A_1-0AWG-MFG 3174.88,804.5 r90 top
T14 "Turret" "CONN_ 0300-2-15-01-47-01-10-0" 1466.58,1802.14 r0 top
T15 "Turret" "CONN_ 0300-2-15-01-47-01-10-0" 614.71,1802.14 r0 top
T16 "Turret" "CONN_ 0300-2-15-01-47-01-10-0" 1466.58,1506.87 r0 top
T17 "Turret" "CONN_ 0300-2-15-01-47-01-10-0" 614.71,1506.87 r0 top
TP1 "" Keystone5126 1893.73,6899.5 r90 top
TP2 "" Keystone5126 1688.73,6899.5 r0 top
TP3 "" Keystone5126 1483.73,6724.5 r0 top
TP4 "" Keystone5126 1688.73,6724.5 r0 top
TP5 "" Keystone5126 2208.73,7074.5 r0 top
TP6 "+3P3V Pullup" Keystone5126 1073.73,6899.5 r0 top
TP7 "+5V Pullup" Keystone5126 868.73,6899.5 r0 top
TP8 "GD EXTERNAL" Keystone5126 1625.4,7074.5 r0 top
TP9 "" Keystone5126 868.73,6724.5 r0 top
TP10 "" Keystone5126 458.73,6724.5 r0 top
TP11 "" Keystone5126 847.62,7074.5 r0 top
TP12 "" Keystone5126 1042.06,7074.5 r0 top
TP13 "" Keystone5126 1278.73,6899.5 r0 top
TP14 "" Keystone5126 1483.73,6899.5 r0 top
TP15 "PGND" Keystone5011 664.22,6899.5 r0 top
TP16 "VIN" Keystone5126 458.73,6899.5 r0 top
TP17 "" Keystone5126 2508.73,6899.5 r0 top
TP18 "" Keystone5126 2508.73,6724.5 r0 top
TP19 "" Keystone5126 1819.84,7074.5 r0 top
TP20 "" Keystone5126 1073.73,6724.5 r0 top
TP21 "" Keystone5126 458.73,7074.5 r0 top
TP22 "VOUT" Keystone5126 2303.73,6899.5 r0 top
TP27 "" Keystone5126 2303.73,6724.5 r0 top
TP29 "" Keystone5126 663.73,6724.5 r0 top
TP30 "" Keystone5126 653.17,7074.5 r0 top
TP31 "" Keystone5126 1278.73,6724.5 r0 top
TP32 "" Keystone5126 1236.51,7074.5 r0 top
TP33 "" Keystone5126 1430.95,7074.5 r0 top
TP34 "" Keystone5126 2098.73,6724.5 r0 top
TP35 "" Keystone5126 1893.73,6724.5 r0 top
TP36 "" Keystone5126 2098.73,6899.5 r0 top
TP39 "" Keystone5126 2014.28,7074.5 r0 top
U1 "TPS259850RQP" RQP0026A-MFG 1888.63,4359.28 r90 top locked
U2 "TPS259850RQP" RQP0026A-MFG 1888.63,5303.48 r90 top
U3 "TPS259850RQP" RQP0026A-MFG 1888.63,4377 r270 bottom
U4 "TPS259850RQP" RQP0026A-MFG 1887.94,3416.29 r90 top
U5 "TPS259850RQP" RQP0026A-MFG 1887.94,3398.37 r270 bottom
U6 "TPS259850RQP" RQP0026A-MFG 1888.63,2470.89 r90 top
U7 "LM94022BIMG/NOPB" DCK0005A_N 1888.63,5718.9 r270 top
U8 "LM94022BIMG/NOPB" DCK0005A_N 1888.63,4840.23 r270 top
U9 "INA241A1IDDF" DDF0008A-MFG 3094.63,7500.82 r270 top
U10 "LM94022BIMG/NOPB" DCK0005A_N 1893.39,2943 r270 top
U11 "LM94022BIMG/NOPB" DCK0005A_N 1888.63,3896.04 r270 top
U12 "UCC27511AQDBVRQ1" DBV0006A_N 2608.8,5821.38 r270 bottom
U13 "UCC27511AQDBVRQ1" DBV0006A_N 2504.98,5839.49 r180 top
U14 "TLV76033DBZR" DBZ0003A_N 857.25,6122.04 r180 bottom
U15 "TLV76050DBZR" DBZ0003A_N 1282.53,6184.37 r0 top
U16 "SN74LVC1G123YZPR" YZP0008ADAD 1198.89,7439.93 r90 top
ZZ1 "This Assembly Note is for PCB labels only" AssemblyNoteLabel 4574.13,237.54 r90 top
ZZ2 "These assemblies are ESD sensitive, ESD precautions shall be observed." AssemblyNote 4334.13,2742.54 r90 top
ZZ3 "These assemblies must be clean and free from flux and all contaminants. Use of no clean flux is not acceptable." AssemblyNote 4099.13,1192.54 r90 top
ZZ4 "These assemblies must comply with workmanship standards IPC-A-610 Class 2, unless otherwise specified." AssemblyNote 3859.13,1517.54 r90 top

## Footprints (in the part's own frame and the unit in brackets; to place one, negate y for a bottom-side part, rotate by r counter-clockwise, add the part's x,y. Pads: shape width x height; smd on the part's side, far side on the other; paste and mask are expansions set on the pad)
0402 [mm] "0402 from SM-752 data"
  rect 0.8x0.6 smd: 1(-0.6,0) 2(0.6,0)
  silkscreen extent -1.22,-0.52 1.22,0.52, body extent -0.55,-0.3 0.55,0.3, height 0.6
0402L [mm] "0402 from SM-752 data"
  rect 0.6x0.5 smd: 1(-0.5,0) 2(0.5,0)
  silkscreen extent -0.13,-0.38 0.13,0.38, body extent -0.55,-0.3 0.55,0.3, height 0.6
0603 [mm] "0603 from SM-752 data"
  rect 1x0.95 smd: 1(-0.8,0) 2(0.8,0)
  silkscreen extent -1.52,-0.69 1.52,0.69, body extent -0.87,-0.47 0.87,0.47, height 1
0603L [mm] "0603 from SM-752 data"
  rect 0.8x0.85 smd: 1(-0.7,0) 2(0.7,0)
  silkscreen extent -0.07,-0.33 0.07,0.33, body extent -0.87,-0.47 0.87,0.47, height 1
0603S [mil]
  rect 20x35 smd: 1(-30,0) 2(30,0)
  body extent -34,-19 34,19, height 39
0805_HV [mil] "0805 with 30mil clearance between pads"
  rect 50x63 smd: 1(-40,0) 2(40,0)
  silkscreen extent -74,-40 74,40, body extent -43,-29 43,29, height 57
AssemblyNote [mil] "Assembly Note"
AssemblyNoteLabel [mil] "Assembly Note for PCB Labels"
CAPSMT_62_JA0 [mm] "10 x 10mm:  Chemi-Con JA0"
  rect 4.4x2.2 smd mask+0.05: 1(-4.45,0) 2(4.45,0)
  silkscreen extent -6.6,-5.25 5.25,5.25, body extent -5.25,-5.25 5.25,5.25, height 10.5
CE_Mark_5mm [mil] "Minimum text height for CE Mark"
  silkscreen extent -138,-98 138,98
CKG57N [mm] "Chip Capacitor, Body 6.0x5.0x5.0mm,"
  rect 2.6x5.254 smd mask+0.05: 1(-2.65,0) 2(2.65,0)
  silkscreen extent -3.2,-2.8 3.2,2.8, body extent -3.3,-2.75 3.3,2.75, height 5.5
"CONN_ 0300-2-15-01-47-01-10-0" [mil] "Mill-Max"
  round 70 hole 42: 1(0,0)
  body extent -39,-39 39,39, height 211
CONN_PEC03SAAN [mm] "SULLINS"
  rect 1.5x1.5 hole 1.016: 1(-2.54,0)
  round 1.5 hole 1.016: 2(0,0) 3(2.54,0)
  silkscreen extent -4.72,-1.27 3.81,1.27, body extent -3.84,-1.3 3.84,1.3, height 8.38
DBV0006A_N [mm] "SOT23, 6-Leads, Body 2.9x1.6mm, Pitch 0.95mm, Lead Span 2.8mm, IPC Medium Density"
  rrect17% 1x0.6 smd: 1(-1.375,0.95) 2(-1.375,0) 3(-1.375,-0.95) 4(1.375,-0.95) 5(1.375,0) 6(1.375,0.95)
  silkscreen extent -1.68,-1.55 0.5,1.55, body extent -1.42,-1.46 1.42,1.46, height 1.12
DBZ0003A_N [mm] "SOT23, 3-Leads, Body 2.9x1.3mm, Pitch 0.95mm, Lead Span 2.4mm, IPC Medium Density"
  rrect17% 1x0.6 smd mask+0.05: 1(-1.2,0.95) 2(-1.2,-0.95) 3(1.2,0)
  silkscreen extent -1.4,-1.5 0.7,1.78, body extent -1.26,-1.46 1.26,1.46, height 0.98
DCK0005A_N [mm] "SOT353, 5-Leads, Body 2x1.3mm, Pitch 0.65mm, Lead Span 2.1mm, IPC Medium Density"
  rrect25% 0.85x0.4 smd mask+0: 1(-1.125,0.65) 2(-1.125,0) 3(-1.125,-0.65) 4(1.125,-0.65) 5(1.125,0.65)
  silkscreen extent -1.48,-1.02 0.55,1.1, body extent -1.14,-1 1.14,1, height 0.95
DDF0008A-MFG [mm]
  rrect22% 1.05x0.45 smd paste+0 mask+0: 1(-1.3,0.975) 2(-1.3,0.325) 3(-1.3,-0.325) 4(-1.3,-0.975) 5(1.3,-0.975) 6(1.3,-0.325) 7(1.3,0.325) 8(1.3,0.975)
  silkscreen extent -2.5,-1.48 0.4,1.47, body extent -1.92,-1.73 1.92,1.72, height 0.25
DNK0008A [mm] "SON, 8-Leads, Body 5x6mm"
  rrect39% 0.86x0.51 smd paste-0.05 mask-0.05: 1(-2.82,1.905) 2(-2.82,0.635) 3(-2.82,-0.635) 4(-2.82,-1.905) 5(2.82,-1.905) 6(2.82,-0.635) 7(2.82,0.635) 8(2.82,1.905)
  rrect8% 1.48x1.27 on Top Paste: 9(-0.18,-1.47) 9(-0.18,0) 9(-0.18,1.47) 9(1.5,-1.47) 9(1.5,0) 9(1.5,1.47)
  rrect5% 4.34x4.6 smd paste-3 mask-0.05: 9(1.08,0)
  silkscreen extent -3.2,-2.7 3.2,2.7, body extent -3.05,-2.55 3.05,2.55, height 1.06
FCC_disclaimer [mil]
Fiducial10-20 [mm]
  round 1 smd mask+0.5: 1(0,0)
FP-B1-0-PCB-L_WIRE_LUG_150A_1-0AWG-MFG [mil]
  rrect100% 96.62x448.62 hole 425 slot 73 at 0 deg paste-99999 mask+0: 1(-380,0) 1(380,0)
  silkscreen extent -320,-289 320,289, body extent -432,-292 432,292, height 10
FP-BZX84-A4V7,215_SOT23-3-MFG [mm]
  rrect17% 0.7x0.6 smd paste+0 mask+0: 1(-1,0.95) 2(-1,-0.95) 3(1,0)
  silkscreen extent -1.4,-1.5 0.7,1.78, body extent -1.15,-1.45 1.15,1.45, height 1.1
FP-C0603C473J3RAC7867_0603-MFG [mm]
  rrect13% 0.75x0.9 smd paste+0 mask+0: 1(-0.6,0) 2(0.6,0)
  silkscreen extent -0.87,-0.82 0.87,0.82, body extent -0.8,-0.4 0.8,0.4, height 0.87
FP-CR160000F_0603-MFG [mm]
  rrect15% 0.65x0.9 smd paste+0 mask+0: 1(-0.725,0) 2(0.725,0)
  silkscreen extent 0,-0.45 0,0.45, body extent -1.15,-0.55 1.15,0.55, height 0.25
FP-CSS2H-3920R-1L00F_3920-MFG [mm]
  rrect4% 2.7x6.2 smd paste+0 mask+0: 1(-4.15,0) 2(4.15,0)
  silkscreen extent -2.42,-2.75 2.42,2.75, body extent -5,-2.6 5,2.6, height 1.02
FP-GCG1885G1H220JA01D_0603-IPC_C [mil]
  rrect12% 33.67x31.97 smd paste+0 mask+0: 1(-24.63,0) 2(24.63,0)
  silkscreen extent -41,-33 41,33, body extent -31,-16 31,16, height 36
FP-GCJ188R71H223KA01D_0603-MFG [mm]
  rrect15% 0.75x0.9 smd paste+0: 1(-0.675,0) 2(0.675,0)
  silkscreen extent -0.9,-0.79 0.9,0.77, body extent -0.8,-0.4 0.8,0.4, height 0.9
FP-GCJ188R71H333KA12D_0603-MFG [mm]
  rrect15% 0.75x0.9 smd paste+0 mask+0: 1(-0.675,0) 2(0.675,0)
  silkscreen extent -0.9,-0.79 0.9,0.77, body extent -0.8,-0.4 0.8,0.4, height 0.9
FP-PEC02DABN_HDR4-MFG [mm]
  rrect6% 1.57x1.57 hole 1.02 paste-2539.97 mask+0: 1(-1.27,-1.27)
  round 1.57 hole 1.02 paste-2539.97 mask+0: 2(-1.27,1.27) 3(1.27,-1.27) 4(1.27,1.27)
  silkscreen extent -3.33,-2.61 2.8,2.61, body extent -2.9,-2.71 2.9,2.71, height 0.25
FP-PMEG045V100EPE-QZ_CFP15B-MFG [mm]
  rrect6% 1.6x1.54 smd paste+0 mask+0: 1(-1.065,2.83) 2(1.065,2.83)
  rrect3% 3.8x5.06 smd paste+0 mask+0: 3(0,-1.07)
  silkscreen extent -2.27,-2.95 3.81,2.95, body extent -2.3,-3.7 2.3,3.7, height 0.25
FP-PTS830GM140SMTRLFS_SMT_3MM05_2MM6-MFG [mm]
  rrect14% 0.7x0.75 smd paste+0 mask+0: 1(-1.6,0.825) 2(1.6,0.825) 3(-1.6,-0.825) 4(1.6,-0.825)
  silkscreen extent -2.65,-1.45 1.67,1.45, body extent -2.05,-1.55 2.05,1.55, height 0.25
FP-RC0603JR-0710RL_0603-MFG [mm]
  rrect13% 0.9x0.8 smd paste+0 mask+0: 1(-0.85,0) 2(0.85,0)
  silkscreen extent 0,-0.45 0,0.45, body extent -0.8,-0.4 0.8,0.4, height 0.55
FP-SI2306BDS-T1-GE3_SOT23-3-MFG [mil]
  rrect18% 29x22 smd paste+0 mask+0: 1(-39,37.5) 2(-39,-37.5) 3(39,0)
  silkscreen extent -50,-60 28,80, body extent -57,-64 57,64, height 10
FP-SMW51R0JT_5329-IPC_C [mm]
  rrect6% 4.5x3.4 smd paste+0 mask+0: 1(-6.75,0) 2(6.75,0)
  silkscreen extent -6.9,-3.8 6.9,3.8, body extent -7.22,-3.9 7.22,3.9, height 0.25
Harwin_D3082-05 [mm] "Shorting Plug, 10.16mm spacing, TH"
  round 1.8 hole 1.3: 1(-5.08,0) 2(5.08,0)
  silkscreen extent -3.9,-0.53 3.9,0.53, body extent -5.6,-0.52 5.61,0.52, height 6.63
IEC_HotSurface_Small [mil]
  silkscreen extent -107,-93 107,92
Keystone5011 [mil] "Keystone Multipurpose loops"
  round 87 hole 63: 1(0,0)
  silkscreen extent -70,-70 70,70, body extent -63,-63 63,62, height 319
Keystone5126 [mil] "Keystone Multipurpose loops"
  round 87 hole 63: 1(0,0)
  silkscreen extent -70,-70 70,70, body extent -63,-63 63,62, height 319
Keystone_1902C [mil] "Hex Standoff, 4-40 threaded, nylon"
  round 1 on Mech4: 0(0,0)
  body extent -145,-126 146,126, height 501
KMQ_1600x2500 [mm] "TH, 2-Leads, 16mm Dia, Pin Spacing 7.5mm"
  rect 1.55x1.55 hole 1.05: 1(-3.75,0)
  round 1.55 hole 1.05: 2(3.75,0)
  silkscreen extent -8.25,-8.25 8.25,8.25, body extent -8.19,-8.24 8.23,8.24, height 26.51
LG_R971_GREEN [mm] "SMD, 2-Leads, Body 2x1.25mm"
  rect 1.2x1.2 smd mask+0.05: 1(-1.05,0) 2(1.05,0)
  silkscreen extent -2.4,-1 1.5,1.65, body extent -1.05,-0.67 1.05,0.67, height 0.91
LS_R976_RED [mm] "SMD, 2-Leads, Body 2x1.25mm"
  rrect8% 1.2x1.2 smd mask+0.05: 1(-1.05,0) 2(1.05,0)
  silkscreen extent -0.26,-0.68 0.26,0.67, body extent -1.05,-0.68 1.05,0.68, height 0.9
"NY PMS 440 0025 PH" [mm] "4-40 nylon screw and mounting hole"
  round 8 hole 3.2 unplated: 1(0,0)
  body extent -3.3,-3.3 3.3,3.3, height 2.69
RQP0026A-MFG [mm]
  round 0.394 smd paste-1000 mask+0: 1(-2.219,1.719) 22(2.219,1.719)
  rrect50% 0.7x0.2 smd paste+0 mask+0: 2(-2.35,1.2) 3(-2.35,0.8) 4(-2.35,0.4) 5(-2.35,0) 6(-2.35,-0.4) 7(-2.35,-0.8) 8(-2.35,-1.2) 15(2.35,-1.2) 16(2.35,-0.8) 17(2.35,-0.4) 18(2.35,0) 19(2.35,0.4) 20(2.35,0.8) 21(2.35,1.2)
  round 0.371 smd paste-1000 mask+0: 9(-2.219,-1.706) 14(2.219,-1.706)
  rrect40% 0.25x2.65 smd paste-1000 mask+0: 10(-1.582,-1.125) 11(-0.677,-1.125) 12(0.228,-1.125) 13(1.132,-1.125) 23(1.582,1.125) 24(0.677,1.125) 25(-0.228,1.125) 26(-1.132,1.125)
  Top Layer region: -2.65,1.5 -2.669,1.504 -2.685,1.515 -2.696,1.531 -2.7,1.55 -2.7,1.55 -2.7,1.85 -2.696,1.869 -2.685,1.885 -2.669,1.896 -2.65,1.9 -2.65,1.9 -2.35,1.9 -2.35,2.4 -2.346,2.419 -2.335,2.435 -2.319,2.446 -2.3,2.45 -2.3,2.45 -2.05,2.45 -2.025,2.443 -2.007,2.425 -2,2.4 -2,2.4 -2,1.55 -2.007,1.525 -2.025,1.507 -2.05,1.5 -2.05,1.5
  Top Layer region: 2.65,-1.5 2.669,-1.504 2.685,-1.515 2.696,-1.531 2.7,-1.55 2.7,-1.55 2.7,-1.85 2.696,-1.869 2.685,-1.885 2.669,-1.896 2.65,-1.9 2.65,-1.9 2.35,-1.9 2.35,-2.4 2.346,-2.419 2.335,-2.435 2.319,-2.446 2.3,-2.45 2.3,-2.45 2.05,-2.45 2.025,-2.443 2.007,-2.425 2,-2.4 2,-2.4 2,-1.55 2.007,-1.525 2.025,-1.507 2.05,-1.5 2.05,-1.5
  Top Layer region: 2.65,1.5 2.669,1.504 2.685,1.515 2.696,1.531 2.7,1.55 2.7,1.55 2.7,1.85 2.696,1.869 2.685,1.885 2.669,1.896 2.65,1.9 2.65,1.9 2.35,1.9 2.35,2.4 2.346,2.419 2.335,2.435 2.319,2.446 2.3,2.45 2.3,2.45 2.05,2.45 2.025,2.443 2.007,2.425 2,2.4 2,2.4 2,1.55 2.007,1.525 2.025,1.507 2.05,1.5 2.05,1.5
  Top Layer region: -2.65,-1.5 -2.669,-1.504 -2.685,-1.515 -2.696,-1.531 -2.7,-1.55 -2.7,-1.55 -2.7,-1.85 -2.696,-1.869 -2.685,-1.885 -2.669,-1.896 -2.65,-1.9 -2.65,-1.9 -2.35,-1.9 -2.35,-2.4 -2.346,-2.419 -2.335,-2.435 -2.319,-2.446 -2.3,-2.45 -2.3,-2.45 -2.05,-2.45 -2.025,-2.443 -2.007,-2.425 -2,-2.4 -2,-2.4 -2,-1.55 -2.007,-1.525 -2.025,-1.507 -2.05,-1.5 -2.05,-1.5
  silkscreen extent -3.55,-2.98 2.55,2.98, body extent -2.8,-2.55 2.8,2.55, height 0.25
SMC [mil] "Molded Diode, 2-Leads, Body 6.9x5.8mm, IPC Medium Density, based on OnSemi component dimensions and land patterns"
  rect 110x150 smd mask+1.97: 1(-140.49,0) 2(140.49,0)
  silkscreen extent -221,-123 189,124, body extent -156,-116 156,116, height 91
SULLINS_PEC03DAAN#1 [mm] "SULLINS"
  rect 1.65x1.65 hole 1.016 mask+0: 1(-2.54,-1.27)
  round 1.65 hole 1.016 mask+0: 2(-2.54,1.27) 3(0,-1.27) 4(0,1.27) 5(2.54,-1.27) 6(2.54,1.27)
  silkscreen extent -4.06,-2.79 3.81,2.54, body extent -3.81,-2.54 3.81,2.54, height 8.38
SULLINS_PEC03DAAN#2 [mm] "SULLINS"
  rect 1.65x1.65 hole 1.016: 1(-2.54,-1.27)
  round 1.65 hole 1.016: 2(-2.54,1.27) 3(0,-1.27) 4(0,1.27) 5(2.54,-1.27) 6(2.54,1.27)
  silkscreen extent -4.57,-2.79 3.81,2.54, body extent -3.81,-2.54 3.81,2.54, height 8.38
